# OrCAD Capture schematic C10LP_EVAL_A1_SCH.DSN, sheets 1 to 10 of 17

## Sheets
1 01. Title, Note, Block Diagram: title: Cyclone 10 LP FPGA Evaluation Kit Board; rev: A1; note: 150-0321321-A1     (6XX-44504R)
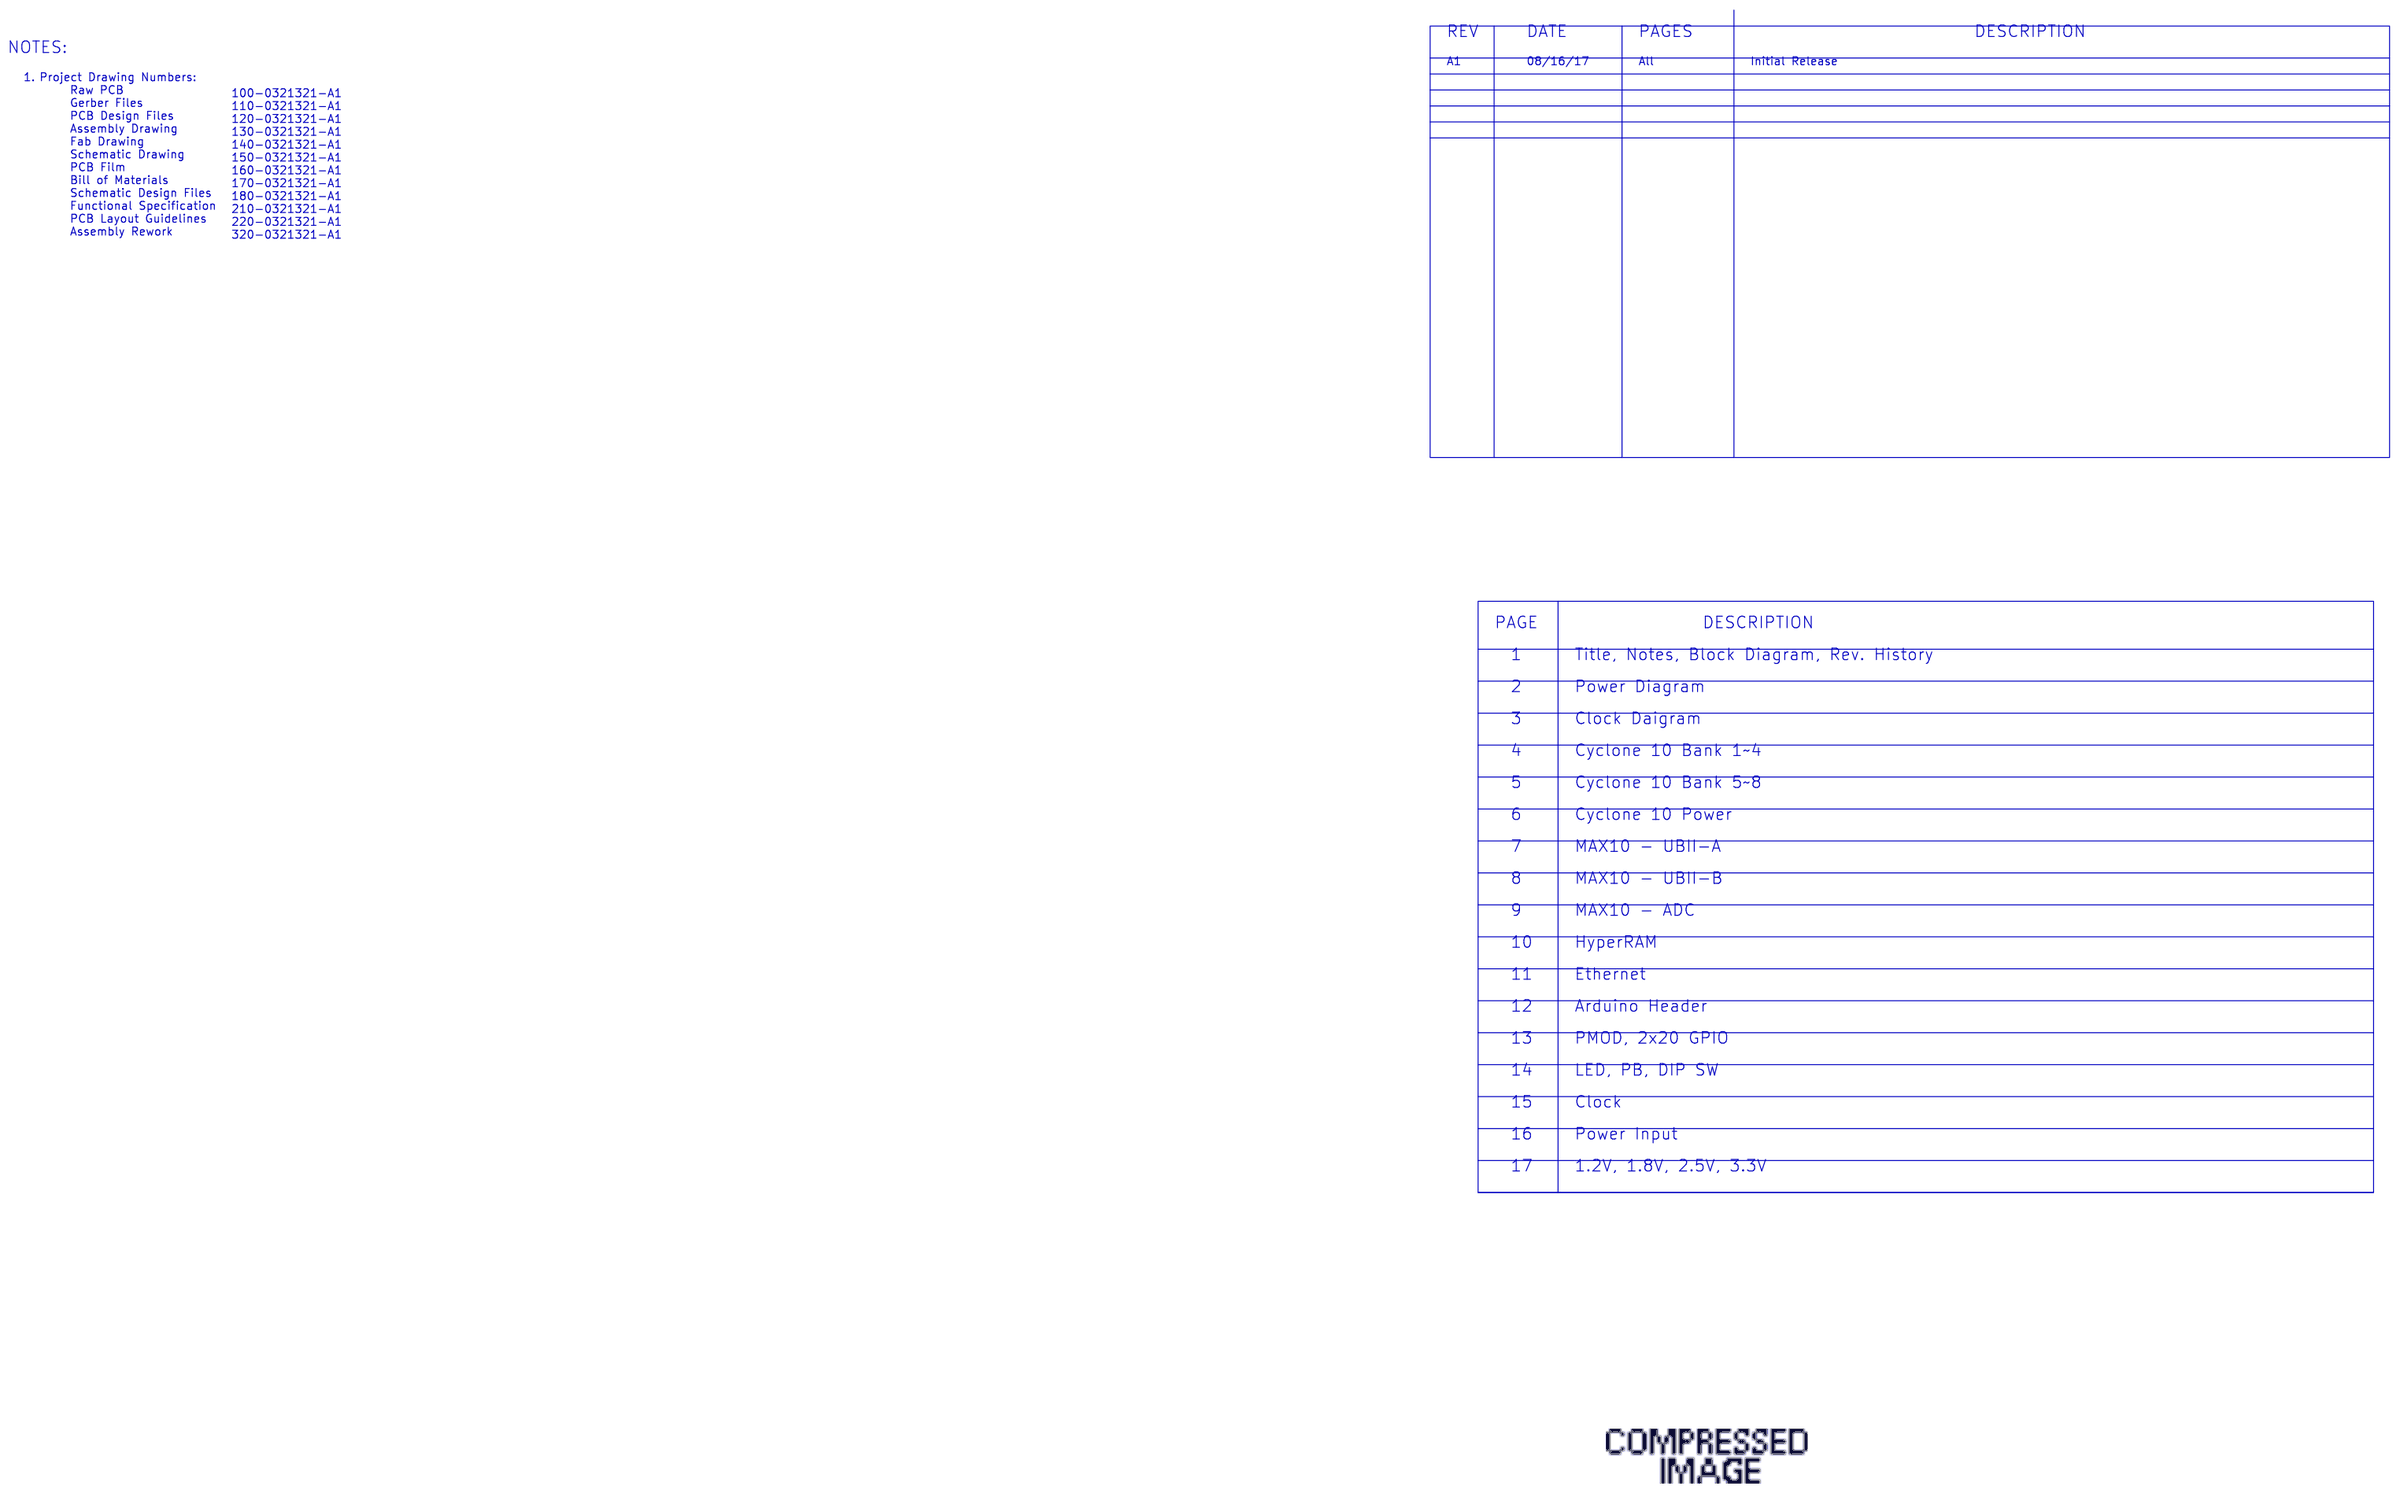
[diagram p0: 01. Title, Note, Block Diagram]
2 02. Power Diagram
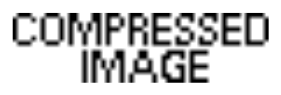
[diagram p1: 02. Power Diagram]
3 03. Clock Daigram
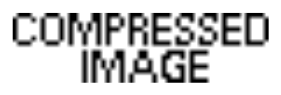
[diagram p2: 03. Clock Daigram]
4 04. Cyclone 10 Bank 1~4: size B
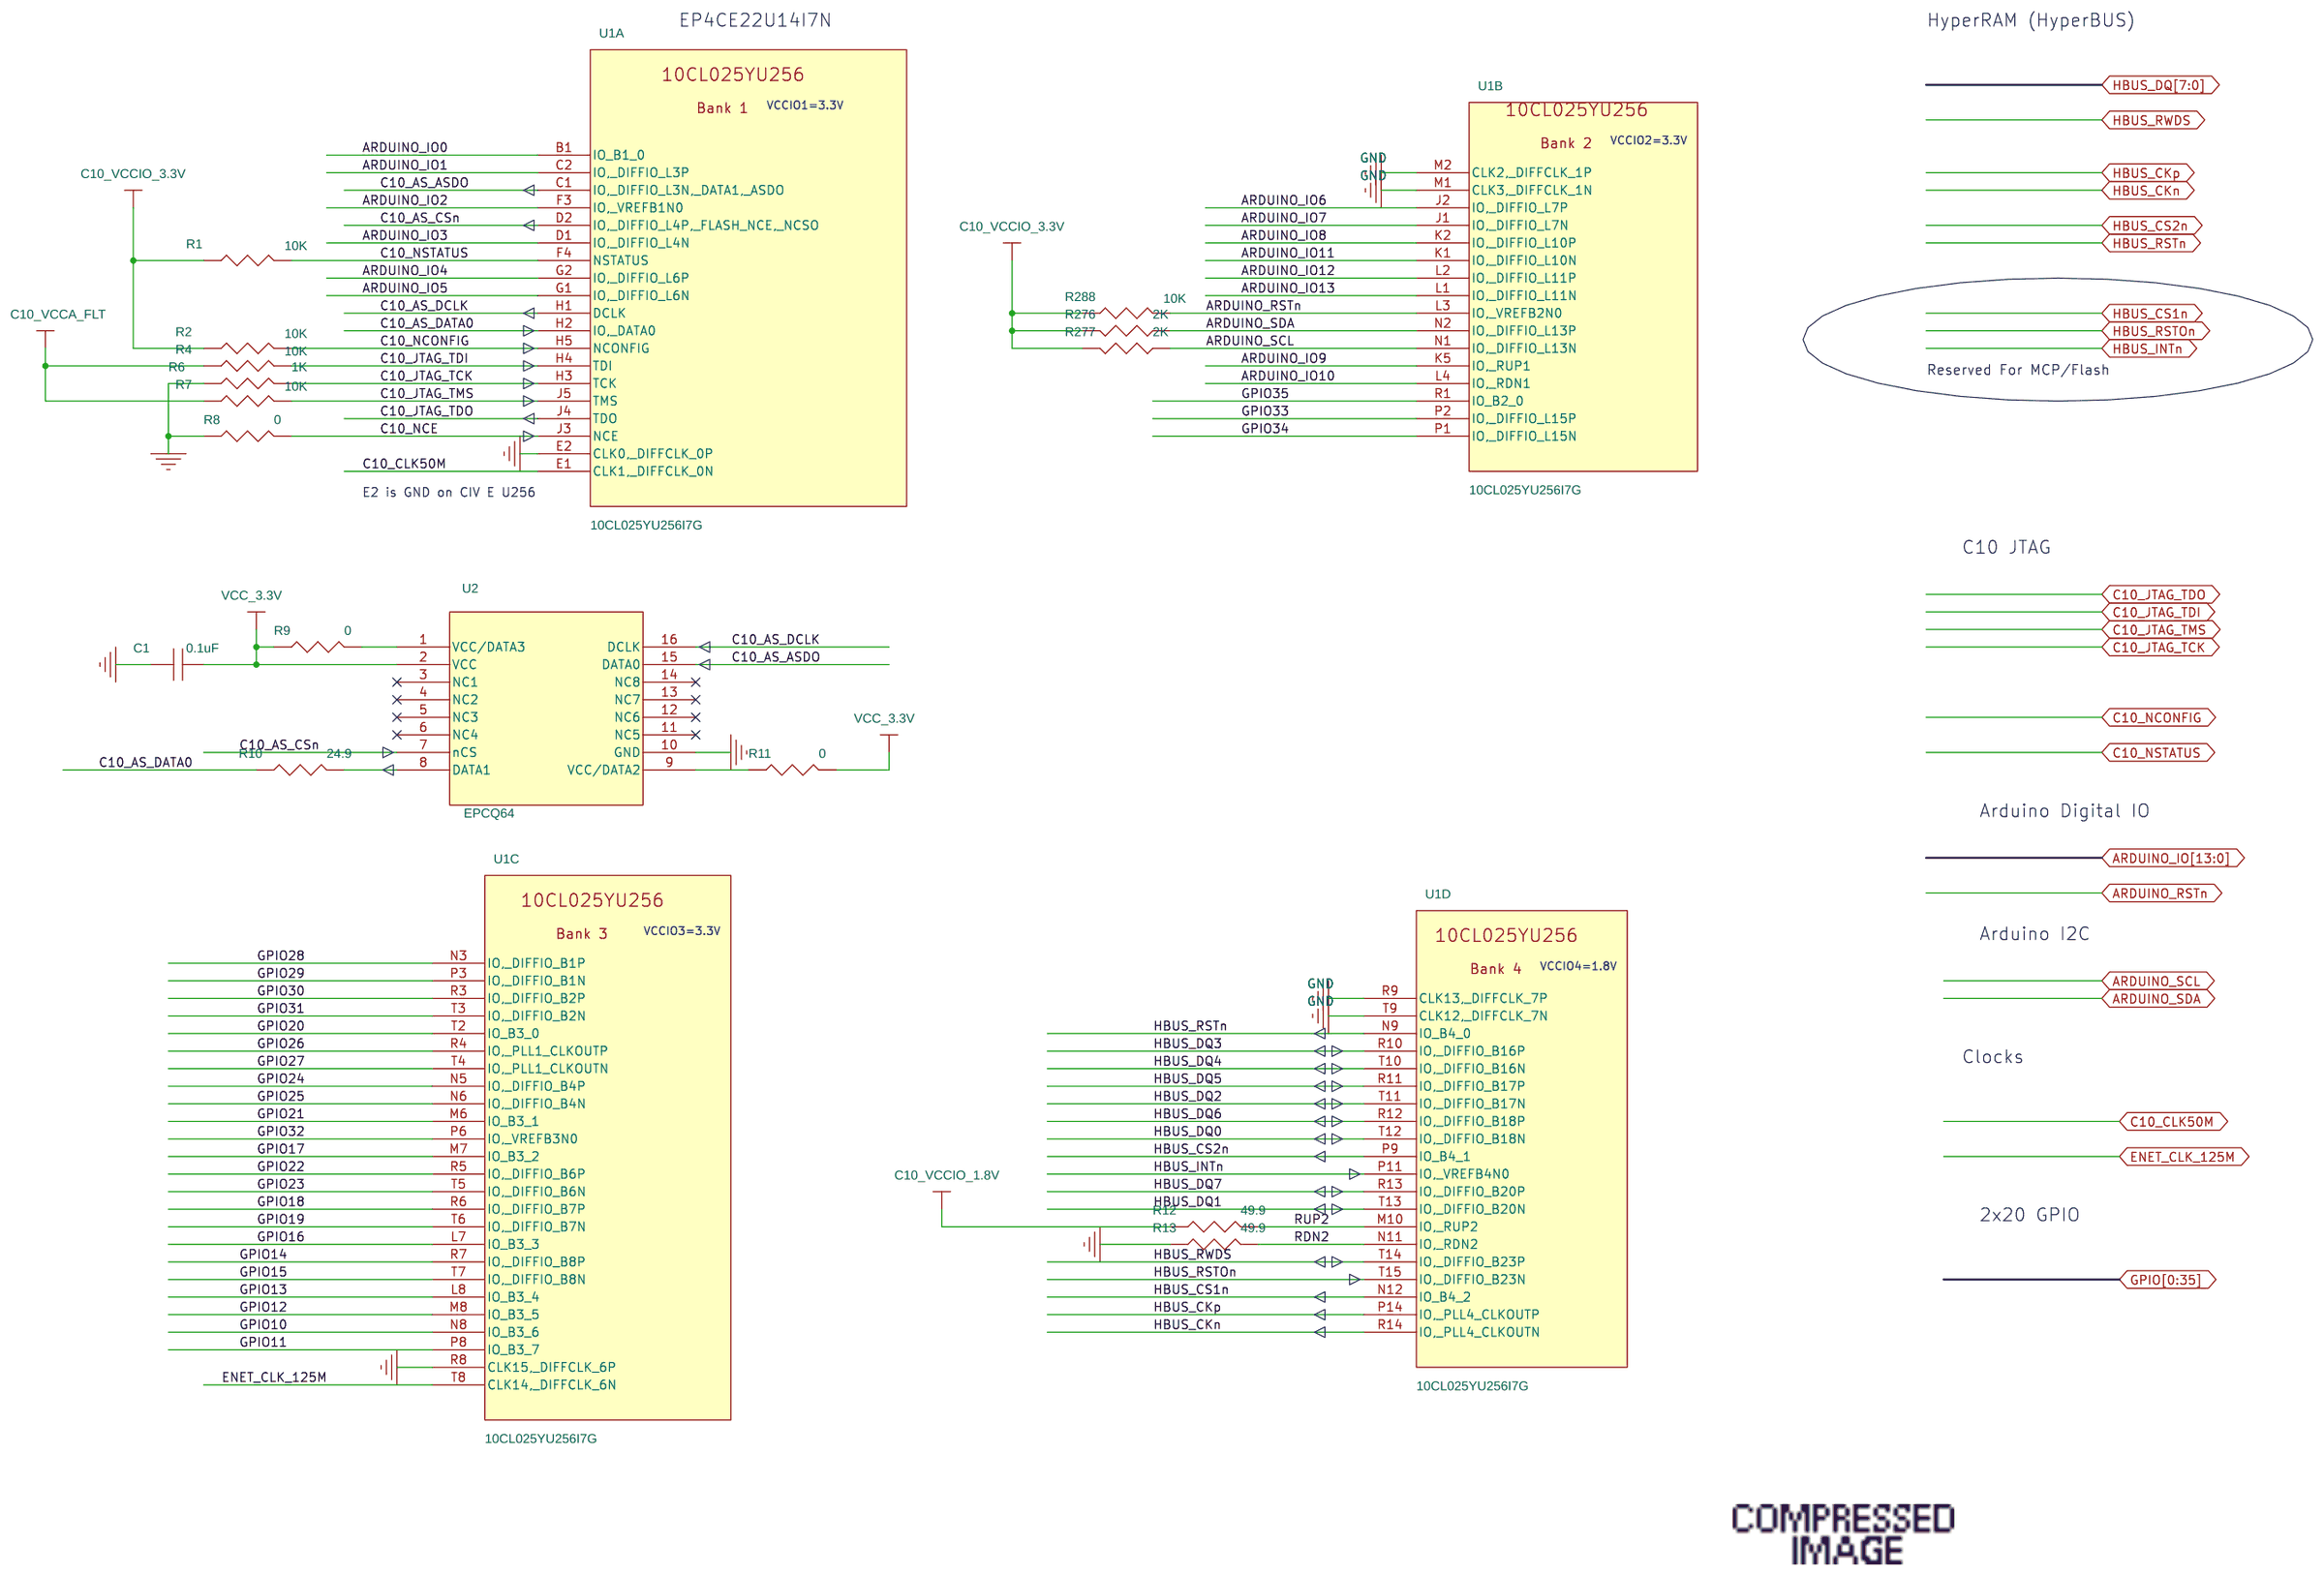
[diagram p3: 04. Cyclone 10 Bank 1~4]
5 05. Cyclone 10 Bank 5~8: size B
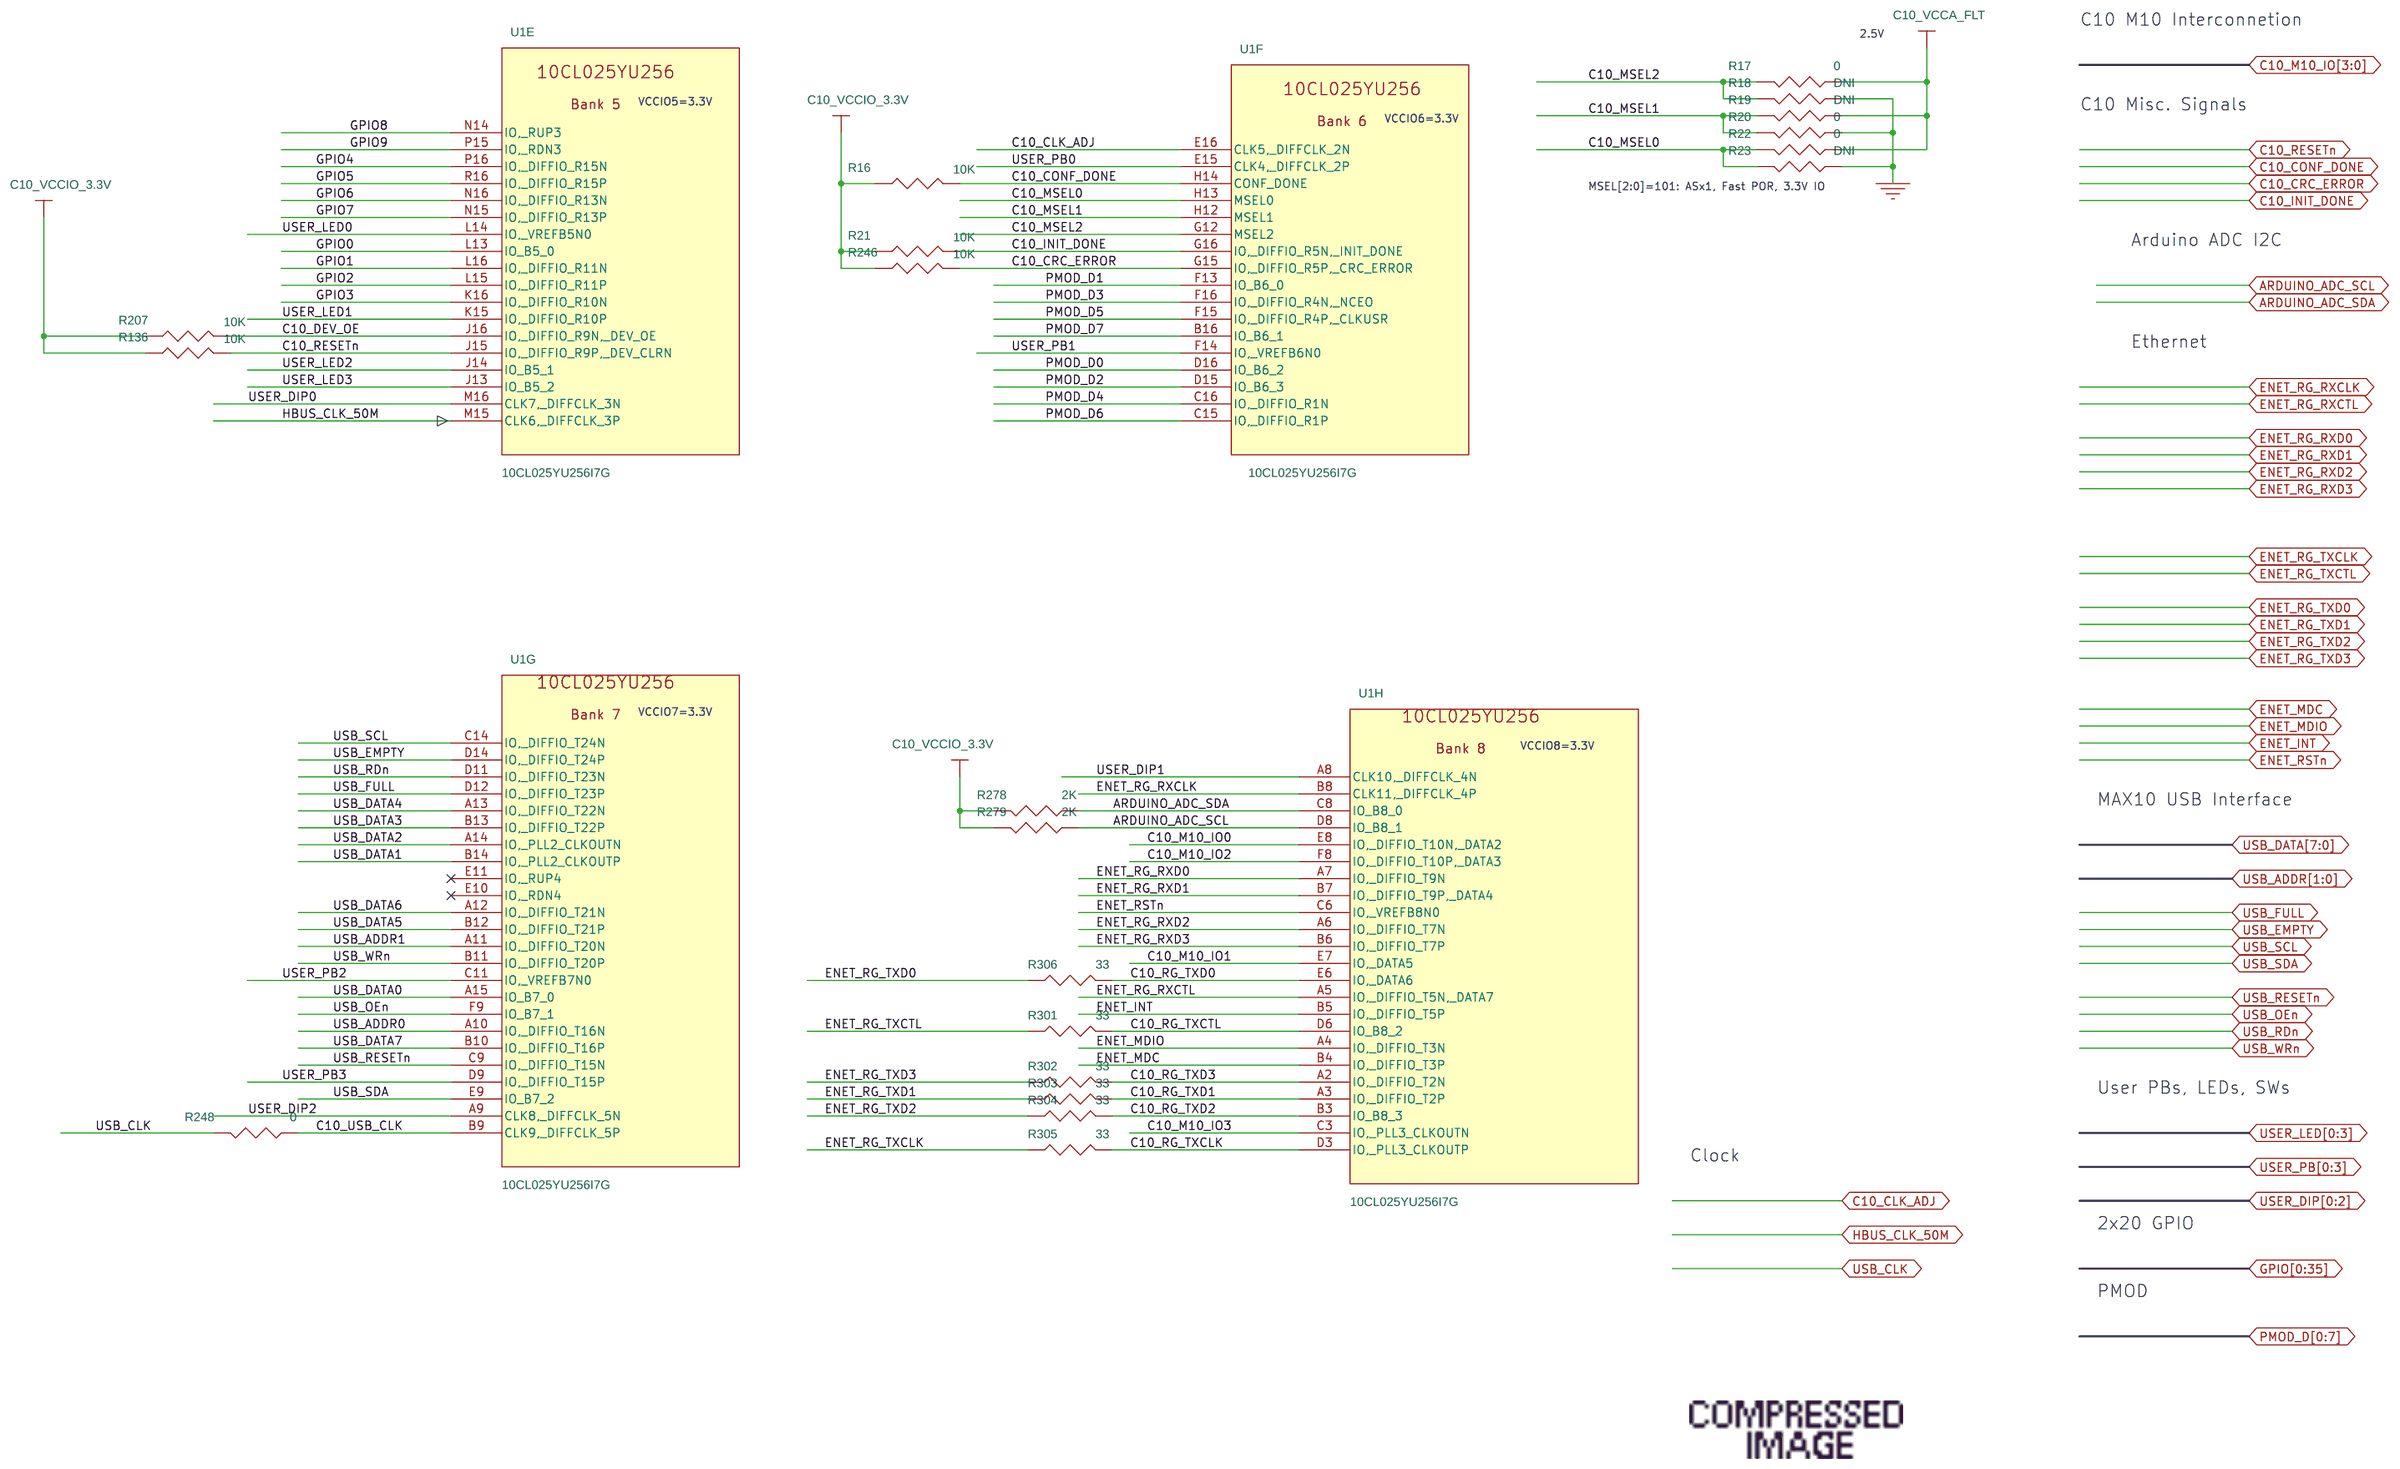
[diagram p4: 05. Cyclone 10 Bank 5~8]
6 06. Cyclone 10 Power: size B
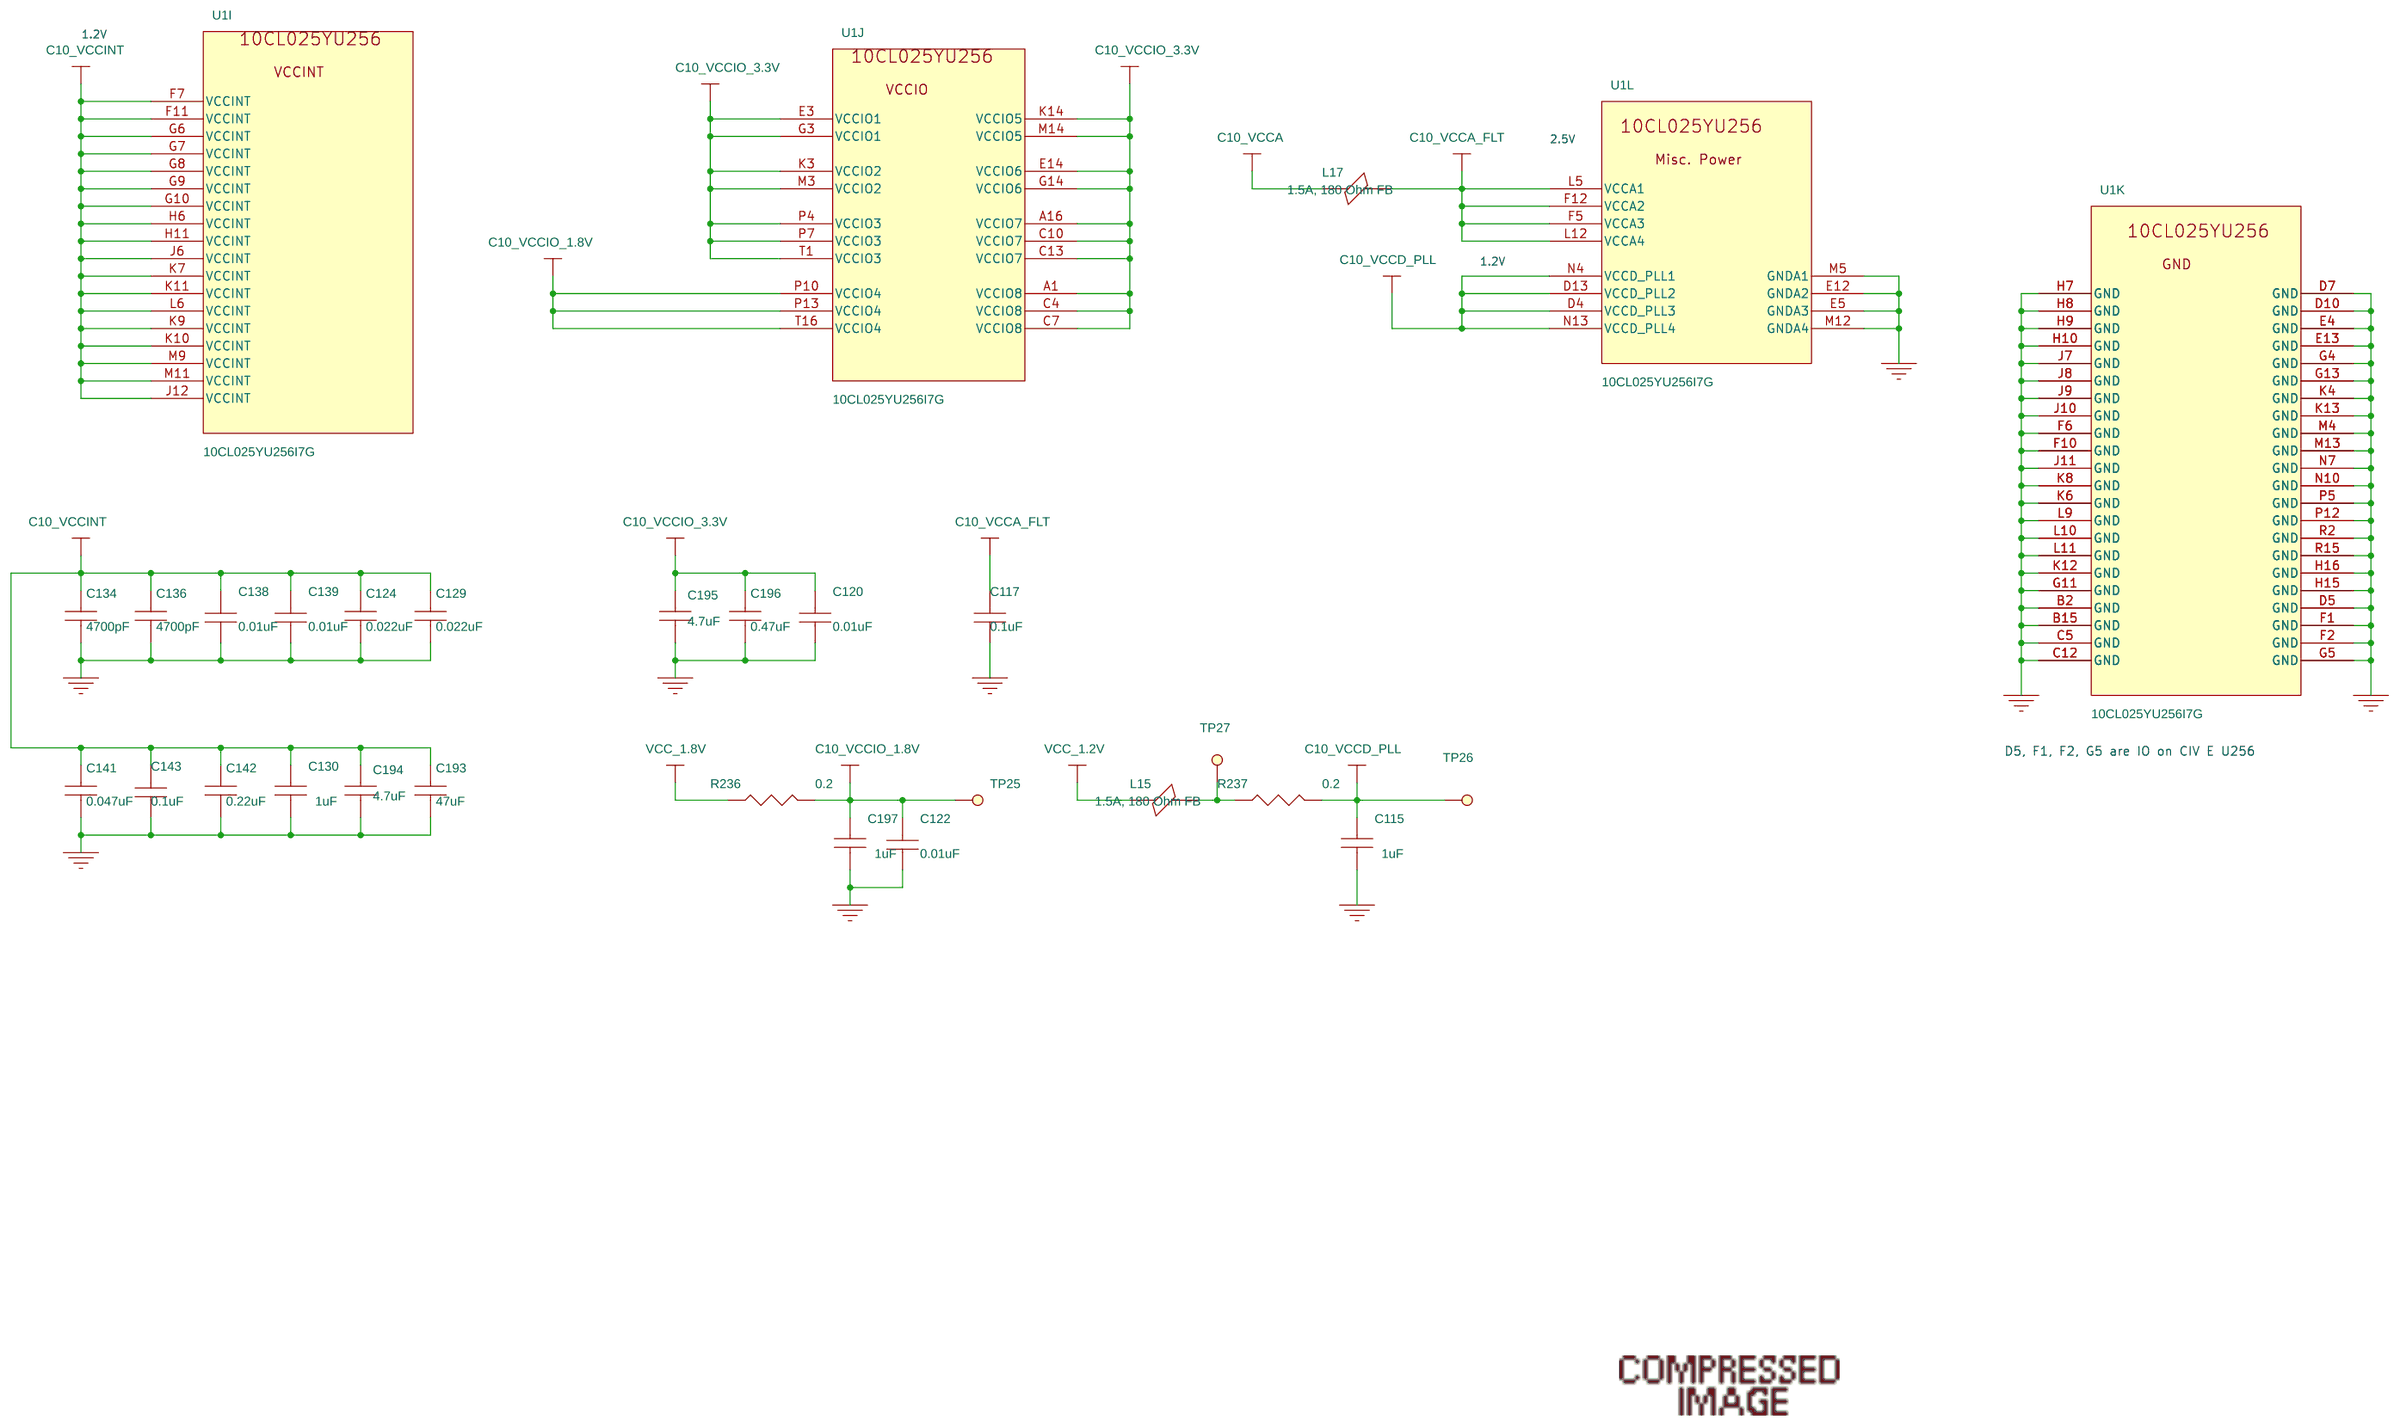
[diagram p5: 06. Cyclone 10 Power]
7 07. MAX10 - UBII-A: size B
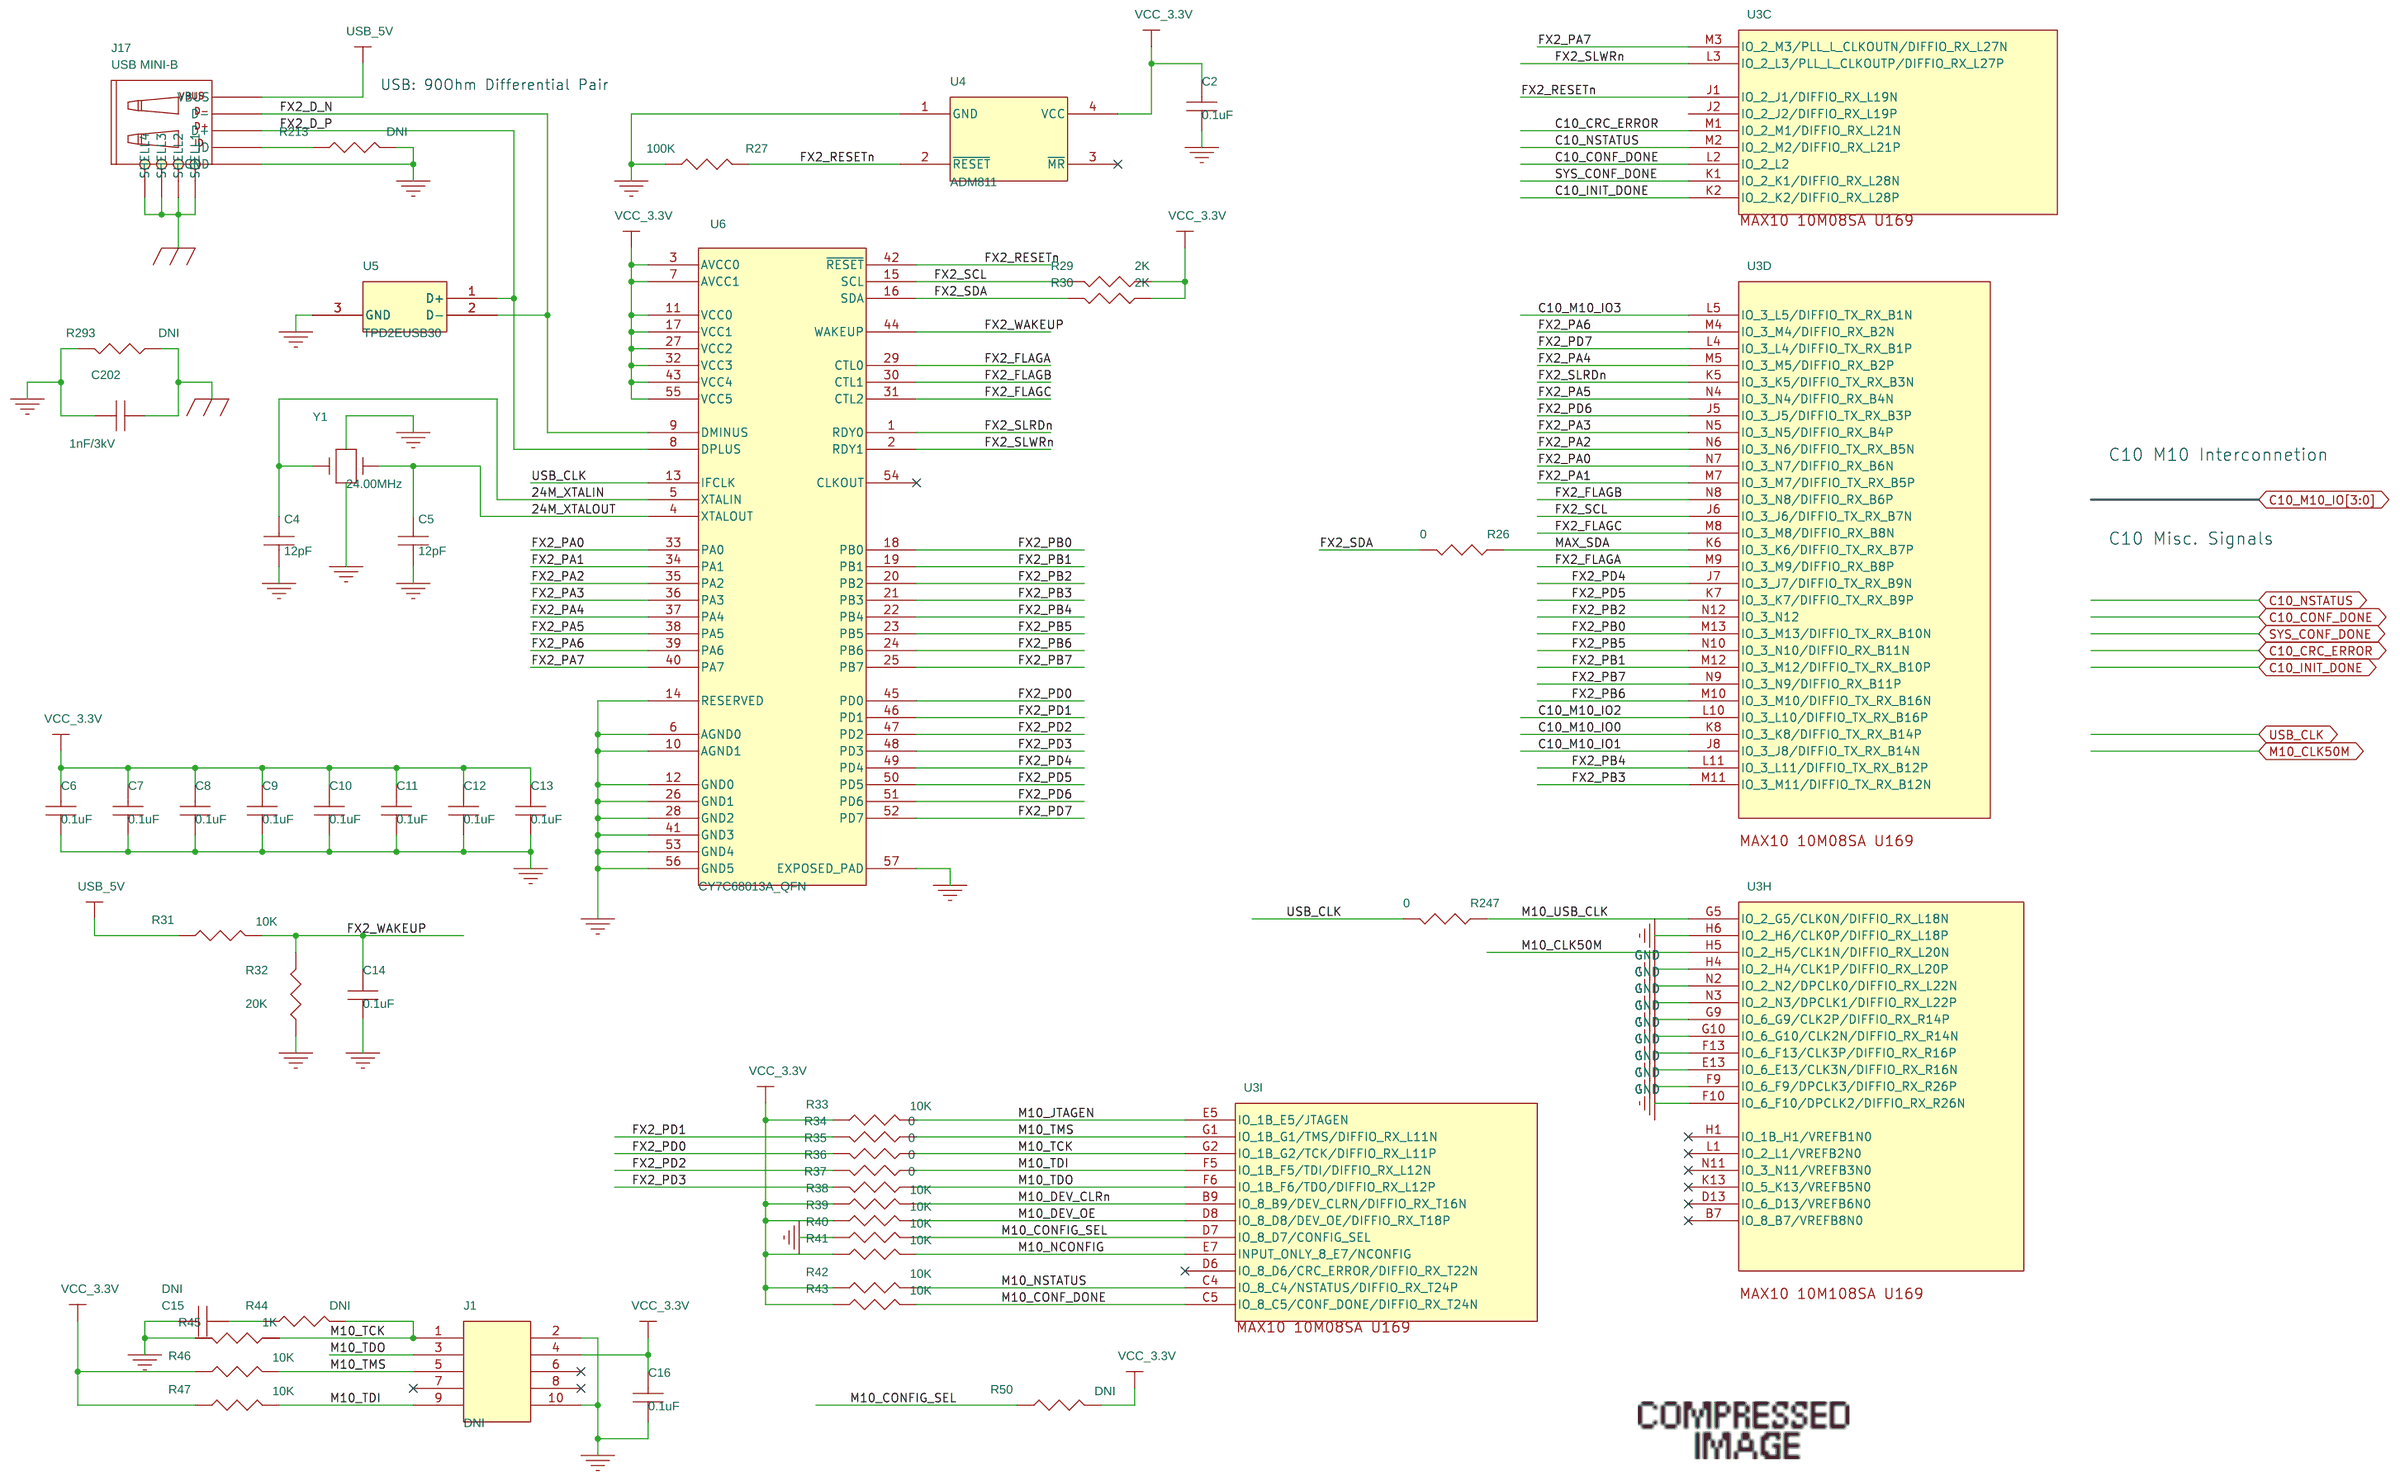
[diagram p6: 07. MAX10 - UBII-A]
8 08. MAX10 - UBII-B: size B
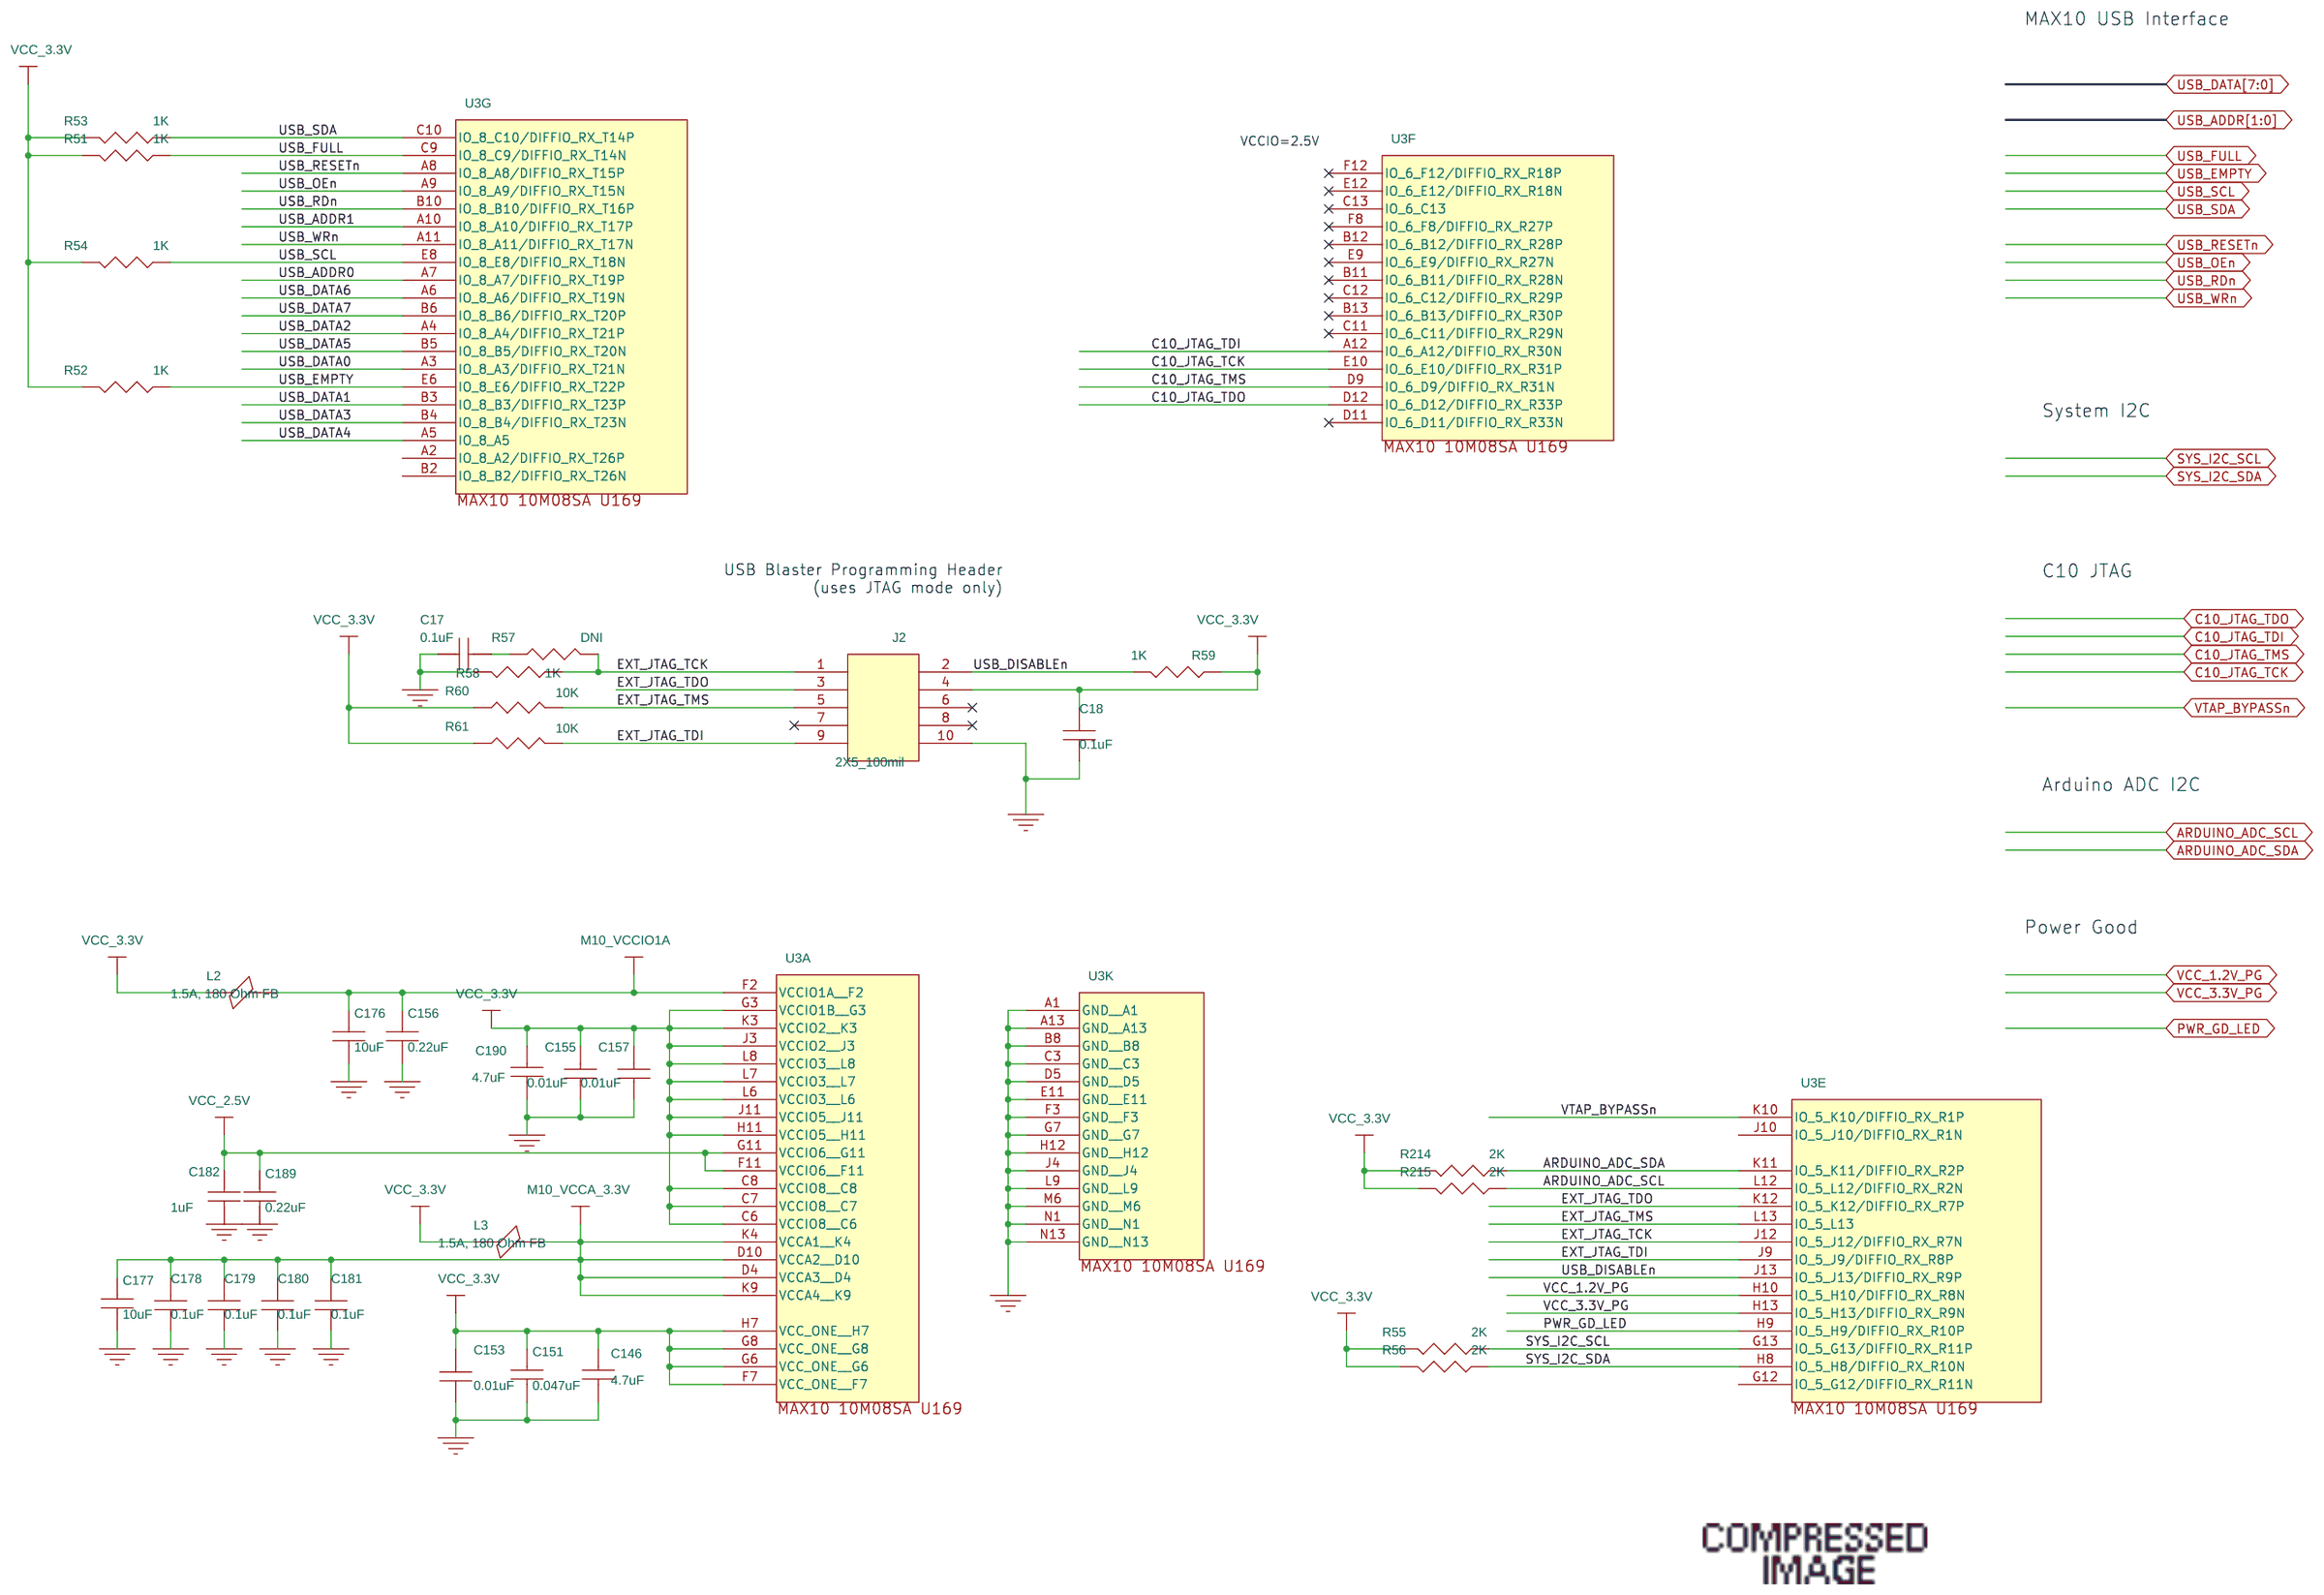
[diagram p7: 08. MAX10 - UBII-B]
9 09. MAX10 - ADC: size B
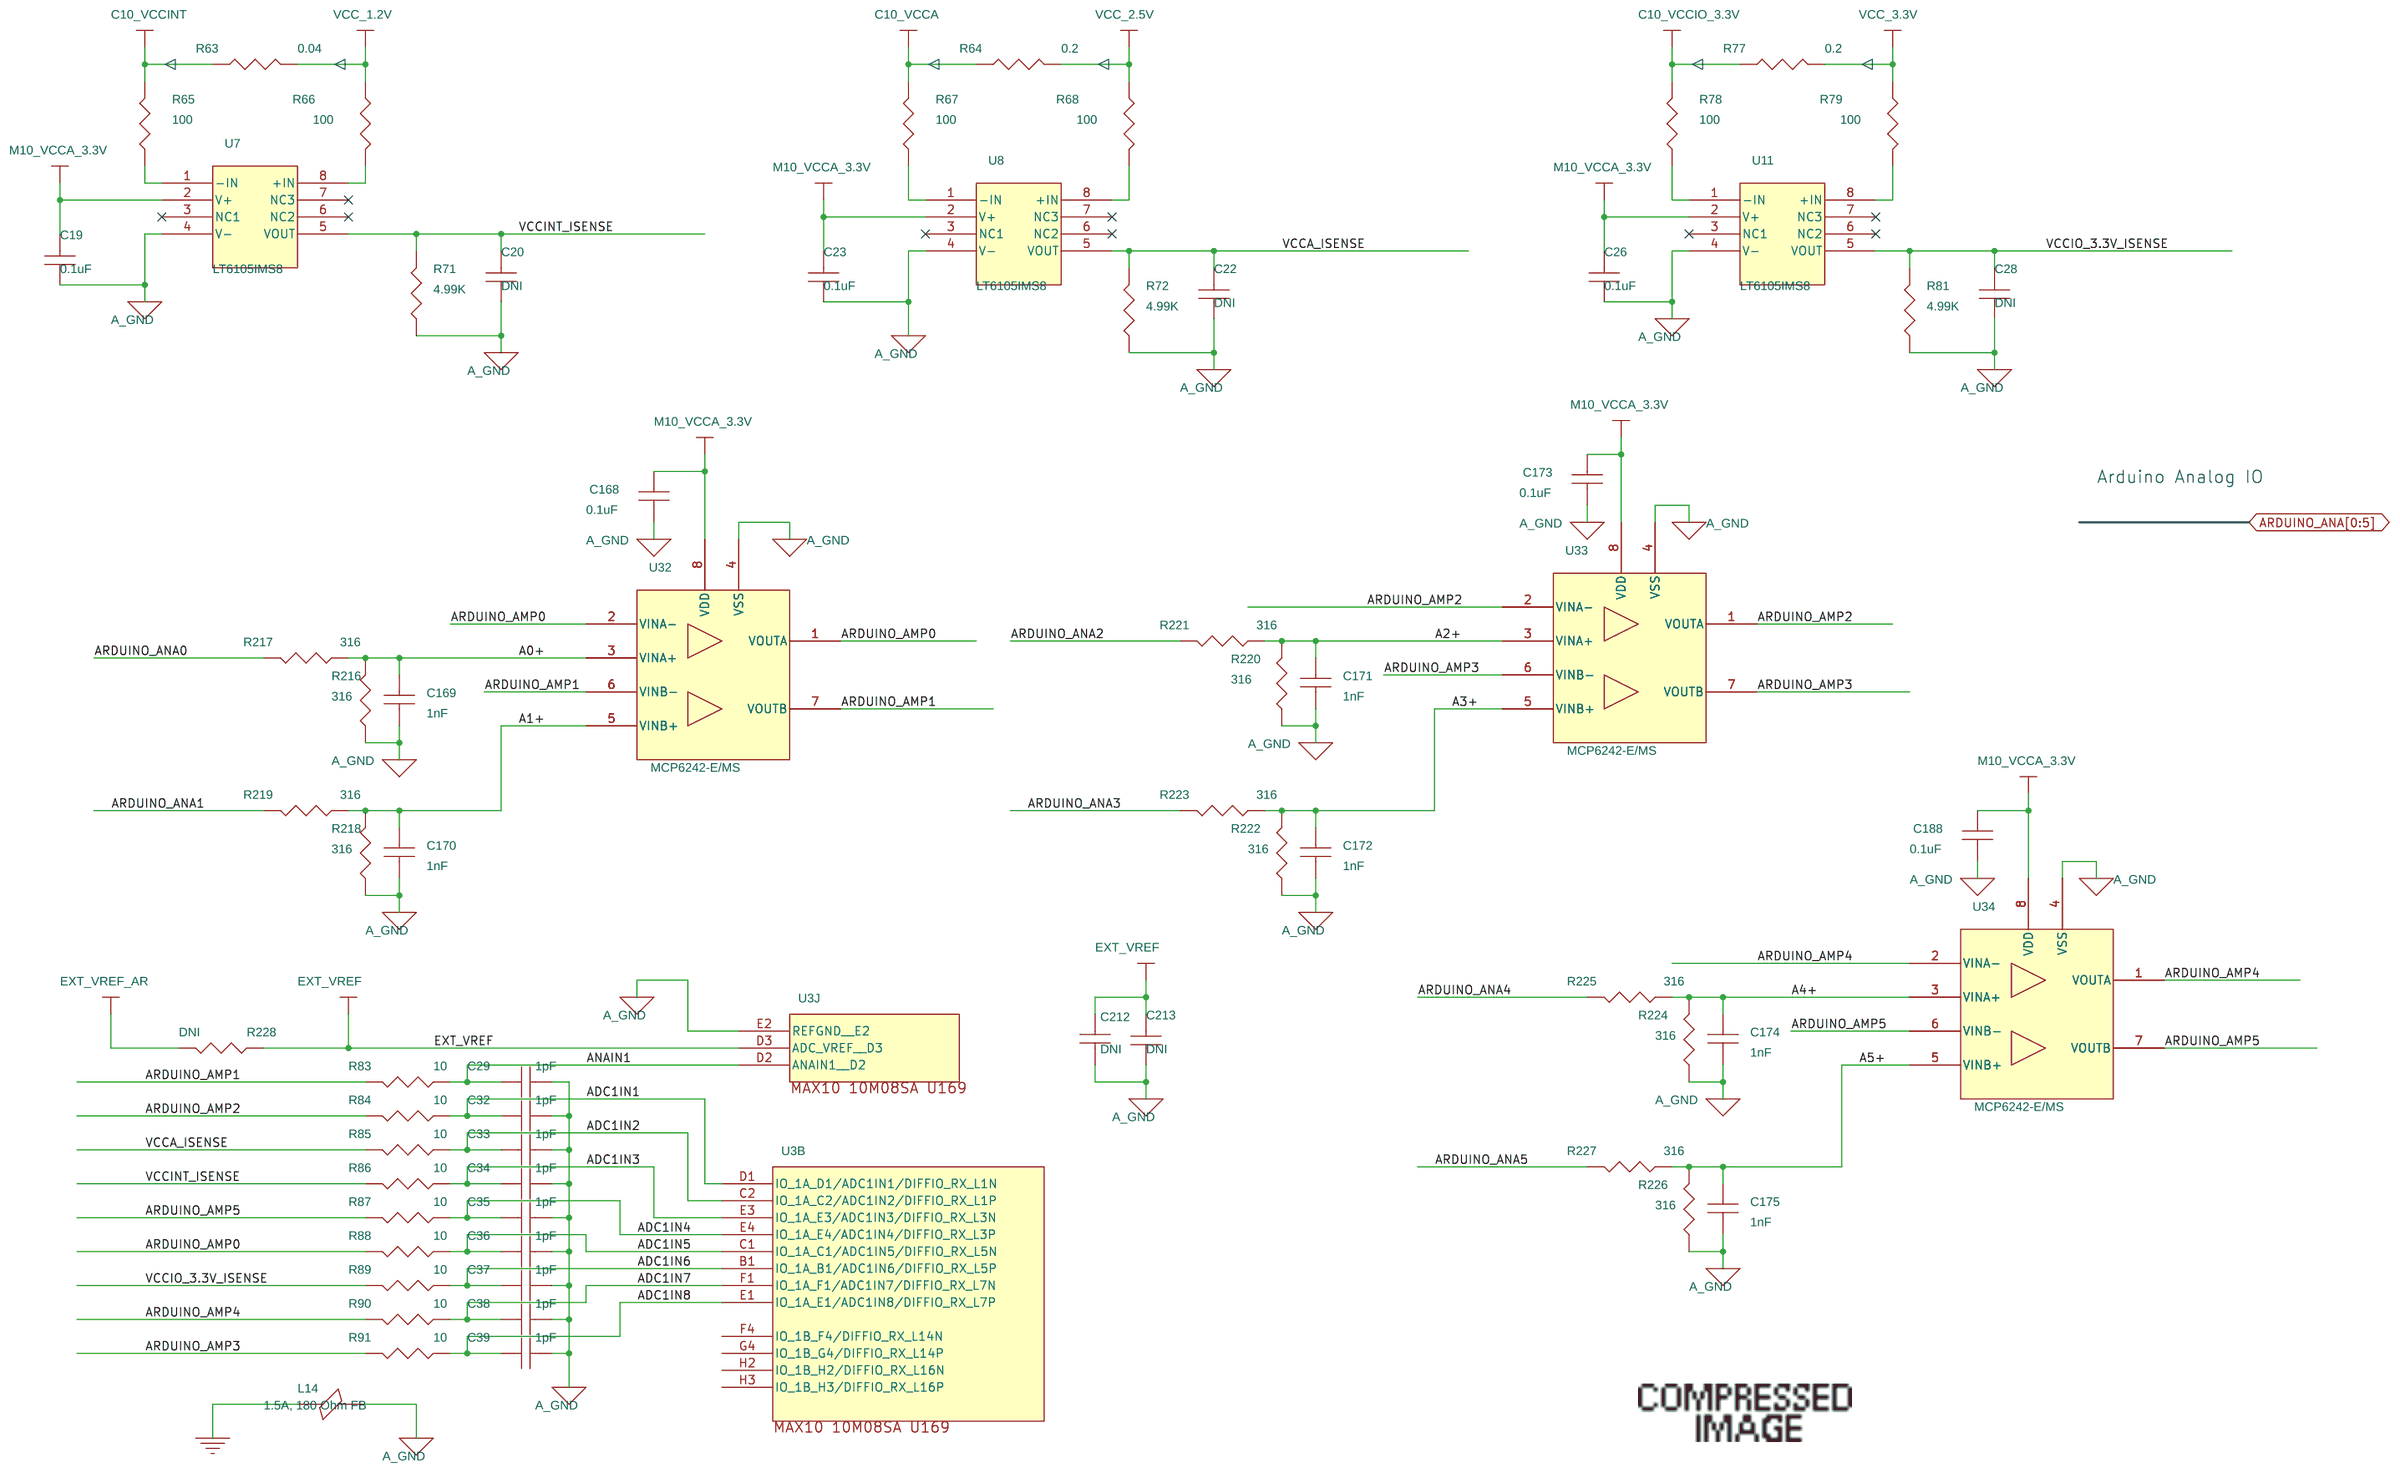
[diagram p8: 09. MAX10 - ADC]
10 10. HyperRAM: size B
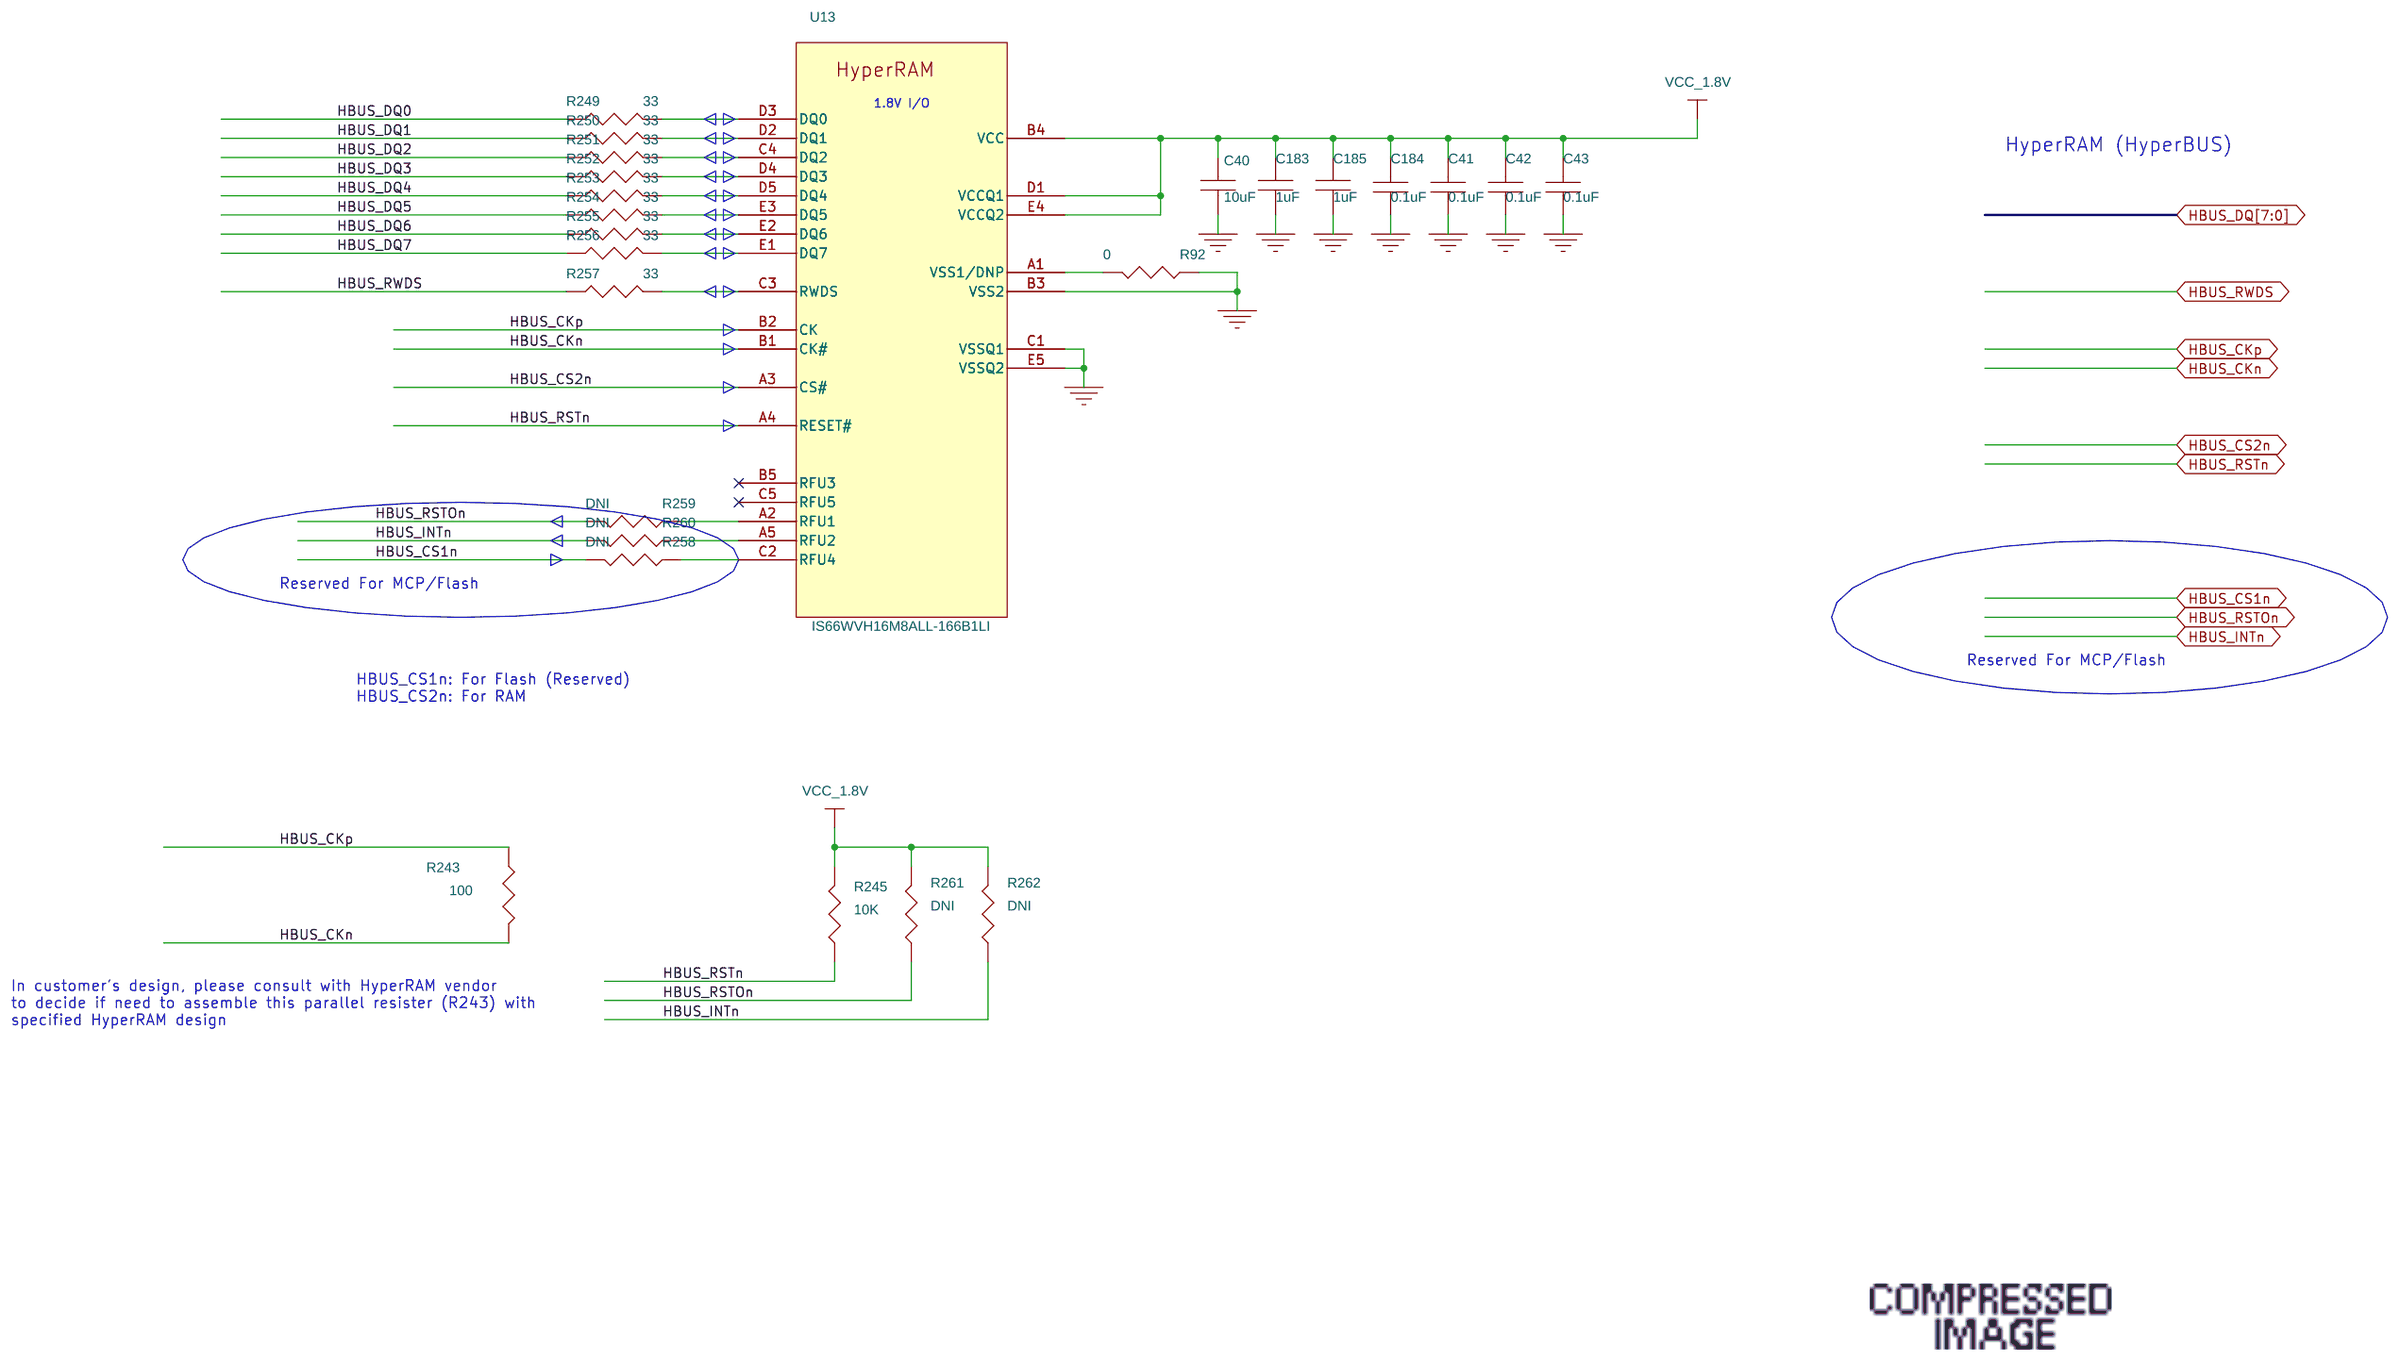
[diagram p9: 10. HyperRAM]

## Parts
sheet 04. Cyclone 10 Bank 1~4
C1  0.1uF  [0402]
R1  10K  [0402]
R2  10K  [0402]
R4  10K  [0402]
R6  1K  [0402]
R7  10K  [0402]
R8  0  [0402]
R9  0  [0402]
R10  24.9  [0402]
R11  0  [0402]
R12  49.9  [0402]
R13  49.9  [0402]
R276  2K  [0402]
R277  2K  [0402]
R288  10K  [0402]
U2  EPCQ64  [SOIC-16_EPCQ]
sheet 05. Cyclone 10 Bank 5~8
R16  10K  [0402]
R17  0  [0402]
R18  DNI  [0402]
R19  DNI  [0402]
R20  0  [0402]
R21  10K  [0402]
R22  0  [0402]
R23  DNI  [0402]
R136  10K  [0402]
R207  10K  [0402]
R246  10K  [0402]
R248  0  [0402]
R278  2K  [0402]
R279  2K  [0402]
R301  33  [0402]
R302  33  [0402]
R303  33  [0402]
R304  33  [0402]
R305  33  [0402]
R306  33  [0402]
U1  10CL025YU256I7G  [U256]  (sections A,B,C,D,E,F,G,H,I,J,K,L)
sheet 06. Cyclone 10 Power
C115  1uF  [C0402_BGA]
C117  0.1uF  [C0402_BGA]
C120  0.01uF  [C0402_BGA]
C122  0.01uF  [C0402_BGA]
C124  0.022uF  [C0402_BGA]
C129  0.022uF  [C0402_BGA]
C130  1uF  [C0402_BGA]
C134  4700pF  [C0402_BGA]
C136  4700pF  [C0402_BGA]
C138  0.01uF  [C0402_BGA]
C139  0.01uF  [C0402_BGA]
C141  0.047uF  [C0402_BGA]
C142  0.22uF  [C0402_BGA]
C143  0.1uF  [C0402_BGA]
C193  47uF  [0805]
C194  4.7uF  [0603]
C195  4.7uF  [0603]
C196  0.47uF  [C0402_BGA]
C197  1uF  [C0402_BGA]
L15  1.5A, 180 Ohm FB  [ind_0603]
L17  1.5A, 180 Ohm FB  [ind_0603]
R236  0.2  [0805]
R237  0.2  [0805]
TP25  VIA_1  [TP_040RD_SMT]
TP26  VIA_1  [TP_040RD_SMT]
TP27  VIA_1  [TP_040RD_SMT]
sheet 07. MAX10 - UBII-A
C2  0.1uF  [0402]
C4  12pF  [0402]
C5  12pF  [0402]
C6  0.1uF  [0402]
C7  0.1uF  [0402]
C8  0.1uF  [0402]
C9  0.1uF  [0402]
C10  0.1uF  [0402]
C11  0.1uF  [0402]
C12  0.1uF  [0402]
C13  0.1uF  [0402]
C14  0.1uF  [0402]
C15  DNI  [0402]
C16  0.1uF  [0402]
C202  1nF/3kV  [1808]
J1  DNI  [hdr2x5_100mil_smt]
J17  USB MINI-B  [Wurth_USB_MINI-B]
R26  0  [0402]
R27  100K  [0402]
R29  2K  [0402]
R30  2K  [0402]
R31  10K  [0402]
R32  20K  [0402]
R33  10K  [0402]
R34  0  [0402]
R35  0  [0402]
R36  0  [0402]
R37  0  [0402]
R38  10K  [0402]
R39  10K  [0402]
R40  10K  [0402]
R41  10K  [0402]
R42  10K  [0402]
R43  10K  [0402]
R44  DNI  [0402]
R45  1K  [0402]
R46  10K  [0402]
R47  10K  [0402]
R50  DNI  [0402]
R213  DNI  [0402]
R247  0  [0402]
R293  DNI  [1206]
U4  ADM811  [SOT-143]
U5  TPD2EUSB30  [DRT]
U6  CY7C68013A_QFN  [QFN56]
Y1  24.00MHz  [XTAL_FA-128]
sheet 08. MAX10 - UBII-B
C17  0.1uF  [0402]
C18  0.1uF  [0402]
C146  4.7uF  [0603]
C151  0.047uF  [C0402_BGA]
C153  0.01uF  [C0402_BGA]
C155  0.01uF  [C0402_BGA]
C156  0.22uF  [C0402_BGA]
C157  0.01uF  [C0402_BGA]
C176  10uF  [0603]
C177  10uF  [0603]
C178  0.1uF  [C0402_BGA]
C179  0.1uF  [C0402_BGA]
C180  0.1uF  [C0402_BGA]
C181  0.1uF  [C0402_BGA]
C182  1uF  [C0402_BGA]
C189  0.22uF  [C0402_BGA]
C190  4.7uF  [0603]
J2  2X5_100mil  [hdr2x5_100mil_smt]
L2  1.5A, 180 Ohm FB  [ind_0603]
L3  1.5A, 180 Ohm FB  [ind_0603]
R51  1K  [0402]
R52  1K  [0402]
R53  1K  [0402]
R54  1K  [0402]
R55  2K  [0402]
R56  2K  [0402]
R57  DNI  [0402]
R58  1K  [0402]
R59  1K  [0402]
R60  10K  [0402]
R61  10K  [0402]
R214  2K  [0402]
R215  2K  [0402]
sheet 09. MAX10 - ADC
C19  0.1uF  [0402]
C20  DNI  [0402]
C22  DNI  [0402]
C23  0.1uF  [0402]
C26  0.1uF  [0402]
C28  DNI  [0402]
C29  1pF  [0402]
C32  1pF  [0402]
C33  1pF  [0402]
C34  1pF  [0402]
C35  1pF  [0402]
C36  1pF  [0402]
C37  1pF  [0402]
C38  1pF  [0402]
C39  1pF  [0402]
C168  0.1uF  [0402]
C169  1nF  [0402]
C170  1nF  [0402]
C171  1nF  [0402]
C172  1nF  [0402]
C173  0.1uF  [0402]
C174  1nF  [0402]
C175  1nF  [0402]
C188  0.1uF  [0402]
C212  DNI  [0603]
C213  DNI  [0402]
L14  1.5A, 180 Ohm FB  [ind_0603]
R63  0.04  [0805]
R64  0.2  [0805]
R65  100  [0402]
R66  100  [0402]
R67  100  [0402]
R68  100  [0402]
R71  4.99K  [0402]
R72  4.99K  [0402]
R77  0.2  [0805]
R78  100  [0402]
R79  100  [0402]
R81  4.99K  [0402]
R83  10  [0402]
R84  10  [0402]
R85  10  [0402]
R86  10  [0402]
R87  10  [0402]
R88  10  [0402]
R89  10  [0402]
R90  10  [0402]
R91  10  [0402]
R216  316  [0402]
R217  316  [0402]
R218  316  [0402]
R219  316  [0402]
R220  316  [0402]
R221  316  [0402]
R222  316  [0402]
R223  316  [0402]
R224  316  [0402]
R225  316  [0402]
R226  316  [0402]
R227  316  [0402]
R228  DNI  [0402]
U3  10M08SAU169  [BGA169-0R80-11X11]  (sections A,B,C,D,E,F,G,H,I,J,K)
U7  LT6105IMS8  [MSOP-8]
U8  LT6105IMS8  [MSOP-8]
U11  LT6105IMS8  [MSOP-8]
U32  MCP6242-E/MS  [MSOP-8]
U33  MCP6242-E/MS  [MSOP-8]
U34  MCP6242-E/MS  [MSOP-8]
sheet 10. HyperRAM
C40  10uF  [0603]
C41  0.1uF  [0402]
C42  0.1uF  [0402]
C43  0.1uF  [0402]
C183  1uF  [0402]
C184  0.1uF  [0402]
C185  1uF  [0402]
R92  0  [0402]
R243  100  [0402]
R245  10K  [0402]
R249  33  [0402]
R250  33  [0402]
R251  33  [0402]
R252  33  [0402]
R253  33  [0402]
R254  33  [0402]
R255  33  [0402]
R256  33  [0402]
R257  33  [0402]
R258  DNI  [0402]
R259  DNI  [0402]
R260  DNI  [0402]
R261  DNI  [0402]
R262  DNI  [0402]
U13  IS66WVH16M8ALL-166B1LI  [TFBGA-24_6x8]

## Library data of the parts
C1 C2 C6-C14 C16-C19 C23 C26 C41-C43 C168 C173 C178-C181 C184 C188 = CAP: CAP CER 0.1UF 25V 20% X7R 0402; Item Num: P03-17618R; Manufacturer: MURATA ELECTRONICS NORTH AMERICA; Manufacturer Part Num: GRM155R71E104KE14D; Num Pins: 2; Part Class: CAPACITORS; Price: 0; RoHS Compliant: RoHS Compliant
R1 R2 R4 R7 R16 R21 R31 R33 R38-R43 R46 R47 R50 R60 R61 R136 R207 R245 R246 R261 R262 R288 = RES_10K_OHM_5%_1_16W_0402_SMD
R6 R45 R51-R54 R58 R59 = R: RES - 1K OHM, 1/16W, 1%, 0402, SMD; Item Num: P02-14274R; Manufacturer: Vishay; Manufacturer Part Num: CRCW04021K00FKED; Price: 0; RoHS Compliant: Yes
R8 R9 R11 = RESISTOR: RES ZERO OHM 1/16W 5% 0402 SMD; Altera Part No.: P02-14020R; Item Num: P02-14020R; Lead Free Status: No; Manufacturer: Panasonic; Manufacturer Part Num: ERJ-2GE0R00X; Num Pins: 2; Part Class: RESISTORS; RoHS Compliant: Yes; Tolerance: 5%
R10 = RES_24.9_OHM_1%_1_16W_0402: RES - 24.9 OHMS, 1%, 1/16W,0402
R12 R13 = RES_49.9_OHM_1%_1_16W_0402
R29 R30 R55 R56 R214 R215 R276-R279 = RESISTOR: RES,2.00K OHMS,1.0%,1/16W,0402; Item Num: P02-11376R; Manufacturer: Panasonic; Manufacturer Part Num: ERJ-2RKF2001X; Price: 0
U2 = EPCQ128: IC CONFIG DEVICE (EPCQ) 64MBIT 16SOIC; Item Num: P01-18138R; Manufacturer: Intel; Manufacturer Part Num: EPCQ64SI16N
R17 R20 R22 R26 R34-R37 R92 R247 R248 = RESISTOR: RES ZERO OHM 1/16W 5% 0402 SMD; Item Num: P02-14020R; Lead Free Status: No; Manufacturer: Panasonic; Manufacturer Part Num: ERJ-2GE0R00X; Num Pins: 2; Part Class: Resistors; RoHS Compliant: Yes
R18 R19 R23 R228 R258-R260 = RESISTOR: RES ZERO OHM 1/16W 5% 0402 SMD; Item Num: P02-14020R; Lead Free Status: No; Manufacturer: Panasonic; Manufacturer Part Num: ERJ-2GE0R00X; Num Pins: 2; Part Class: Resistors; Price: 0; RoHS Compliant: Yes
R249-R257 R301-R306 = RESISTOR: RES 33 OHM 1/16W 5% 0402 SMD; Altera Part No.: P02-14020R; Item Num: P02-14029R; Manufacturer: Panasonic; Manufacturer Part Num: ERJ-2GEJ330X
U1 = 10CL025YU256I7G: IC - CYCLONE 10 LP FPGA, 10CL025YU256I7G, 25K LES, U256 BGA, LEADFREE; Item Num: P01-18144R; Manufacturer: Intel
C115 C130 C182 C183 C185 C197 = CAP_1.0UF_10%_10V_0402: Manufacturer: Murata; Manufacturer Part Num: GRM155R61A105KE15D
C117 C143 = CAP: CAP CER 0.1UF 25V 20% X7R 0402; Item Num: P03-17618R; Manufacturer: MURATA ELECTRONICS NORTH AMERICA; Manufacturer Part Num: GRM155R71E104KE14D
C120 C122 C138 C139 C153 C155 C157 = CAP: CAP - CER, 10NF, 50V, +/-10%, X7R, 0402 SMD; Dielectric: X5R; Item Num: P03-16318R; Manufacturer: Murata; Manufacturer Part Num: GRM155R71H103KA88D
C124 C129 = CAP: CAP - CER 0.022UF, 10V, 10%, X5R, 0402; Item Num: P03-17676R; Manufacturer: Murata; Manufacturer Part Num: GRM155R61A223KA01D
C134 C136 = CAP: CAP - CER 4700PF 50V 10% X7R 0402; Item Num: P03-15074R; Manufacturer: Murata; Manufacturer Part Num: GRM155R71H472KA01D
C141 C151 = CAP: CAP, CERAMIC, 0.047UF, 10%, X7R, 16V, 0402; Item Num: P03-17659R; Manufacturer: Murata; Manufacturer Part Num: GRM155R71C473KA01D
C142 C156 C189 = CAP: CAP - CERAMIC, 0.22UF, 10V, X5R, 10%, 0402; Item Num: P03-15149R; Manufacturer: Murata; Manufacturer Part Num: GRM155R61A224KE19D
C193 = CAP: CAP - CER 47UF, 10V, 20%, X5R, +/-20%, 0805; Item Num: P03-17686R; Manufacturer: TDK Electronics; Manufacturer Part Num: C2012X5R1A476M125AC
C146 C190 C194 C195 = Cap_0.1UF_+_-10%_10V_0402: CAP - CER 4.7UF, 25V, 10%, X5R, 0603; Item Num: P03-17677R; Manufacturer: Murata; Manufacturer Part Num: GRM188R61E475KE11D
C196 = CAP: CAP - CER, 0.47UF, 10%, 6.3V, X5R, 0402; Item Num: P03-15172R; Manufacturer: Murata; Manufacturer Part Num: RM155R60J474KE19D
L2 L3 L14 L15 L17 = IND_Ferrite_0603_3A_30_Ohms: IND - SMD EMI FILTERS/CHIP FERRITE BEAD, 180-OHM @ 100MHZ, 0.09-OHM DCR, 1.5A, 0603; Item Num: P04-17069R; Manufacturer Part Num: 742792624
R64 R77 R236 R237 = RESISTOR: RES  0.2 OHM 1% 1/3W 0805 SMD; Item Num: P02-17884R; Lead Free Status: Yes; Manufacturer: Panasonic; Manufacturer Part Num: ERJ-6BSFR20V; Num Pins: 2; Part Class: Resistors; Price: 0; RoHS Compliant: Yes
TP25-TP27 = VIA_1
C4 C5 = CAP: CAP - 12PF, 50V, +/-5%, CERAMIC, 0402 SMD; Item Num: P03-15352R; Manufacturer: Murata; Manufacturer Part Num: GRM1555C1H120JA01D; RoHS Compliant: RoHS Compliant
C15 C20 C22 C28 C213 = CAP: CAP CER 0.1UF 25V 20% X7R 0402; CAPACITANCE: 0.1uF; Item Num: P03-17618R; Manufacturer: MURATA ELECTRONICS NORTH AMERICA; Manufacturer Part Num: GRM155R71E104KE14D; Num Pins: 2; Part Class: CAPACITORS; Price: 0; RoHS Compliant: RoHS Compliant
C202 = CAP: CAP CER 1000PF 3KV X7R 1808; Item Num: P03-17908R; Manufacturer: Yageo; Manufacturer Part Num: CC1808KKX7REBB102
J1 J2 = 2x5: CONN - CONN HEADER VERT DUAL 10POS 2.54MM; Item Num: P23-38640R; Lead Free Status: No; Manufacturer: Wurth Elektronik; Manufacturer Part Num: 61001021121; Num Pins: 10; Part Class: Connectors; Price: 0; RoHS Compliant: Yes
J17 = USB_MINI-B: CONN - MINI USB 5POS HORIZ T/H; Item Num: P23-38638R; Manufacturer: Wurth Elektronik; Manufacturer Part Num: 651 005 136 521
R27 = RESISTOR: RES,100K OHMS,1.0%,1/16W,0402; Item Num: P02-11386R; Manufacturer: Panasonic; Manufacturer Part Num: ERJ-2RKF1003X; Price: 0
R32 = RESISTOR: RES 20.0K OHM 1/16W 1% 0402 SMD; Item Num: P02-14071R; Manufacturer: Panasonic; Manufacturer Part Num: ERJ-2RKF2002X
R44 R57 = RESISTOR: RES,10.0K OHMS,1.0%,1/16W, 0402; Item Num: P02-11364R; Manufacturer: Panasonic; Manufacturer Part Num: ERJ-2RKF1002X; Num Pins: 2
R213 = RESISTOR: RES ZERO OHM 1/16W 5% 0402 SMD; Altera Part No.: P02-14020R; Item Num: P02-14020R; Lead Free Status: No; Manufacturer: Panasonic; Manufacturer Part Num: ERJ-2GE0R00X; Num Pins: 2; Part Class: RESISTORS; Price: 0; RoHS Compliant: Yes; Tolerance: 5%
R293 = RESISTOR: RES SMD 1M OHM 1% 1/4W 1206; Item Num: P02-17885R; Manufacturer: Panasonic; Manufacturer Part Num: ERJ-8ENF1004V
U4 = MAX811_0: IC SUPVSR W/RESET 2.93V SOT-143; Item Num: P01-18140R; Manufacturer: Analog Device; Manufacturer Part Num: ADM811SARTZ-REEL7
U5 = TPD2EUSB30_0: DIODE - FULL SPEED USB ESD SOLUTION, 2CH, SOT3; Item Num: P08-20777R; Lead Free Status: Yes; MFR_LIFECYCLE: Active; Manufacturer: Texas Instruments; Manufacturer Part Num: TPD2EUSB30DRxx; Num Pins: 3; Part Class: ICS; RoHS Compliant: Yes
U6 = CY7C68013A_0: IC - EZ-USB FX2LP Microcontroller 400KHz, 56-QFN, 3.3V; Item Num: P01-17739R; Lead Free Status: Yes; Manufacturer: Cypress; Manufacturer Part Num: CY7C68013A-56LTXCx; Num Pins: 57; Part Class: ICs; RoHS Compliant: Yes
Y1 = CRYSTAL_SM_13: CRYSTAL - MINI XTL, 24.00 MHZ, +/-50PPM, +/-30PPM-20~75C, 12PF, 2.0mm x 1.6mm SMD; Item Num: P07-19648R; Lead Free Status: Yes; MFR_LIFECYCLE: Active; Manufacturer: Epson Toyocom; Manufacturer Part Num: FA-128 24.0000MB-W:; Num Pins: 4; RoHS Compliant: Yes
C40 C176 C177 C212 = CAP: CAP - CER 10UF 6.3V 20% X5R 0603; Item Num: P03-15733R; Manufacturer: Murata; Manufacturer Part Num: GRM188R60J106ME47X; RoHS Compliant: RoHS Compliant
C29 C32-C39 = CAP: CAP - CERAMIC, 1PF, +/-0.25PF,  50V, 0402, C0G; Item Num: P03-15104R; Manufacturer: Murata; Manufacturer Part Num: GJM1555C1H1R0CB01D
C169-C172 C174 C175 = CAP: CAP CER 1000PF 50V 10% X7R 0402; Item Num: P03-17756R; Manufacturer: Yageo; Manufacturer Part Num: CC0402KRX7R9BB102; Price: 0
R63 = RESISTOR: RES SMD 0.04 OHM 1% 1/8W 0805; Item Num: P02-17911R; Manufacturer: Vishay Dale; Manufacturer Part Num: WSL0805R0400FEA
R65-R68 R78 R79 R243 = RESISTOR: RES,100 OHMS,1.0%,1/16W,0402; Item Num: P02-11381R; Manufacturer: Panasonic; Manufacturer Part Num: ERJ-2RKF1000X; Price: 0
R71 R72 R81 = RESISTOR: RES 4.99K OHM 1/16W 1% 0402 SMD; Item Num: P02-14129R; Manufacturer: Panasonic; Manufacturer Part Num: ERJ-2RKF4991X; Price: 0
R83-R91 = RES_10_OHM_1.0%_1_16W_0402: RES, 10 OHMS, 1.0%, 1/10W, 0402
R216-R227 = RES_10K_OHM_5%_1_16W_0402_SMD: RES - 316 OHM 1/16W 1% 0402 SMD; Item Num: P02-14349R; Manufacturer Part Num: ERJ-2RKF3160X
U3 = 10M16SA_U169_12: IC - MAX 10 10M08 SINGLE-SUPPLY DEVICE, SINGLE ADC BLOCK, 169-PIN UBGA, 3.0 OR 3.3V SUPPLY; Item Num: P01-18141R; Manufacturer: Intel; Manufacturer Part Num: 10M08SAU169C8G
U7 U8 U11 = LT6105IDCB_0: IC OPAMP CURR SENSE 100KHZ 8MSOP; Item Num: P01-18124R; Manufacturer: Linear Technology; Manufacturer Part Num: LT6105IMS8#PBF
U32-U34 = MCP6242-E_MS: IC OPAMP GP 550KHZ RRO 8MSOP; Item Num: P01-18145R; Manufacturer: Microchip Technology Inc.
U13 = IS66WVH32M8ALL-166BLI_0: 128Mb 16MbX8 1.8V 166MHz HyperRAM; Item Num: P01-18125R; Manufacturer: ISSI

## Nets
GND: C1.2 C2.1 C4.2 C5.2 C6.1 C7.1 C8.1 C9.1 C10.1 C11.1 C12.1 C13.1 C14.1 C15.1 C16.1 C17.1 C18.1 C40.2 C41.1 C42.1 C43.1 C115.2 C117.1 C120.1 C122.1 C124.2 C129.2 C130.2 C134.2 C136.2 C138.1 C139.1 C141.2 C142.2 C143.1 C146.2 C151.2 C153.1 C155.1 C156.2 C157.1 C176.2 C177.2 C178.1 C179.1 C180.1 C181.1 C182.2 C183.2 C184.1 C185.2 C189.2 C190.2 C193.2 C194.2 C195.2 C196.2 C197.2 C202.2 J1.2 J1.10 J2.10 J17.5(GND) L14.1 R6.2 R8.1 R13.1 R18.2 R20.2 R23.2 R27.2 R32.1 R40.1 R45.2 R58.2 R92.1 R213.2 R293.1 U1.B2(GND) U1.B15(GND) U1.C5(GND) U1.C12(GND) U1.D5(GND) U1.D7(GND) U1.D10(GND) U1.E2(CLK0,_DIFFCLK_0P) U1.E4(GND) U1.E5(GNDA3) U1.E12(GNDA2) U1.E13(GND) U1.F1(GND) U1.F2(GND) U1.F6(GND) U1.F10(GND) U1.G4(GND) U1.G5(GND) U1.G11(GND) U1.G13(GND) U1.H7(GND) U1.H8(GND) U1.H9(GND) U1.H10(GND) U1.H15(GND) U1.H16(GND) U1.J7(GND) U1.J8(GND) U1.J9(GND) U1.J10(GND) U1.J11(GND) U1.K4(GND) U1.K6(GND) U1.K8(GND) U1.K12(GND) U1.K13(GND) U1.L9(GND) U1.L10(GND) U1.L11(GND) U1.M1(CLK3,_DIFFCLK_1N) U1.M2(CLK2,_DIFFCLK_1P) U1.M4(GND) U1.M5(GNDA1) U1.M12(GNDA4) U1.M13(GND) U1.N7(GND) U1.N10(GND) U1.P5(GND) U1.P12(GND) U1.R2(GND) U1.R8(CLK15,_DIFFCLK_6P) U1.R9(CLK13,_DIFFCLK_7P) U1.R15(GND) U1.T9(CLK12,_DIFFCLK_7N) U2.10(GND) U3.A1(GND_) U3.A13(GND_) U3.B8(GND_) U3.C3(GND_) U3.D5(GND_) U3.E11(GND_) U3.E13(IO_6_E13/CLK3N/DIFFIO_RX_R16N) U3.F3(GND_) U3.F9(IO_6_F9/DPCLK3/DIFFIO_RX_R26P) U3.F10(IO_6_F10/DPCLK2/DIFFIO_RX_R26N) U3.F13(IO_6_F13/CLK3P/DIFFIO_RX_R16P) U3.G7(GND_) U3.G9(IO_6_G9/CLK2P/DIFFIO_RX_R14P) U3.G10(IO_6_G10/CLK2N/DIFFIO_RX_R14N) U3.H4(IO_2_H4/CLK1P/DIFFIO_RX_L20P) U3.H6(IO_2_H6/CLK0P/DIFFIO_RX_L18P) U3.H12(GND_) U3.J4(GND_) U3.L9(GND_) U3.M6(GND_) U3.N1(GND_) U3.N2(IO_2_N2/DPCLK0/DIFFIO_RX_L22N) U3.N3(IO_2_N3/DPCLK1/DIFFIO_RX_L22P) U3.N13(GND_) U4.1(GND) U5.3(GND) U6.6(AGND0) U6.10(AGND1) U6.12(GND0) U6.14(RESERVED) U6.26(GND1) U6.28(GND2) U6.41(GND3) U6.53(GND4) U6.56(GND5) U6.57(EXPOSED_PAD) U13.B3(VSS2) U13.C1(VSSQ1) U13.E5(VSSQ2) Y1.2 Y1.4 ; also on sheet 11 12 13 14 15 16 17
GND_EARTH_USB: C202.1 J17.6(SHELL1) J17.7(SHELL2) J17.8(SHELL3) J17.9(SHELL4) R293.2
VCC_1.2V: L15.1 R63.2 R66.2 ; also on sheet 17
VCC_1.2V_PG: U3.H10(IO_5_H10/DIFFIO_RX_R8N) ; also on sheet 17
VCC_1.8V: C40.1 C41.2 C42.2 C43.2 C183.1 C184.2 C185.1 R236.1 R245.2 R261.2 R262.2 U13.B4(VCC) U13.D1(VCCQ1) U13.E4(VCCQ2) ; also on sheet 17
VCC_2.5V: C182.1 C189.1 R64.2 R68.2 U3.F11(VCCIO6_) U3.G11(VCCIO6_) ; also on sheet 17
VCC_3.3V: C1.1 C2.2 C6.2 C7.2 C8.2 C9.2 C10.2 C11.2 C12.2 C13.2 C16.2 C18.2 C146.1 C151.1 C153.2 C155.2 C157.2 C190.1 J1.4 J2.4 L2.1 L3.1 R9.1 R11.2 R29.2 R30.2 R33.1 R38.1 R39.1 R41.1 R42.1 R43.1 R46.1 R47.1 R50.2 R51.2 R52.2 R53.2 R54.2 R55.1 R56.1 R59.2 R60.1 R61.1 R77.2 R79.2 R214.1 R215.1 U2.2(VCC) U3.C6(VCCIO8_) U3.C7(VCCIO8_) U3.C8(VCCIO8_) U3.F7(VCC_ONE_) U3.G3(VCCIO1B_) U3.G6(VCC_ONE_) U3.G8(VCC_ONE_) U3.H7(VCC_ONE_) U3.H11(VCCIO5_) U3.J3(VCCIO2_) U3.J11(VCCIO5_) U3.K3(VCCIO2_) U3.L6(VCCIO3_) U3.L7(VCCIO3_) U3.L8(VCCIO3_) U4.4(VCC) U6.3(AVCC0) U6.7(AVCC1) U6.11(VCC0) U6.17(VCC1) U6.27(VCC2) U6.32(VCC3) U6.43(VCC4) U6.55(VCC5) ; also on sheet 11 12 13 14 15 17
VCC_3.3V_PG: U3.H13(IO_5_H13/DIFFIO_RX_R9N) ; also on sheet 17
VCCA_ISENSE: C22.2 R72.2 R85.2 U8.5(VOUT)
VCCINT_ISENSE: C20.2 R71.2 R86.2 U7.5(VOUT)
VCCIO_3.3V_ISENSE: C28.2 R81.2 R89.2 U11.5(VOUT)
24M_XTALIN: C4.1 U6.5(XTALIN) Y1.1
24M_XTALOUT: C5.1 U6.4(XTALOUT) Y1.3
A0+: C169.1 R216.2 R217.2 U32.3(VINA+)
A1+: C170.1 R218.2 R219.2 U32.5(VINB+)
A2+: C171.1 R220.2 R221.2 U33.3(VINA+)
A3+: C172.1 R222.2 R223.2 U33.5(VINB+)
A4+: C174.1 R224.2 R225.2 U34.3(VINA+)
A5+: C175.1 R226.2 R227.2 U34.5(VINB+)
A_GND: C19.1 C20.1 C22.1 C23.1 C26.1 C28.1 C29.2 C32.2 C33.2 C34.2 C35.2 C36.2 C37.2 C38.2 C39.2 C168.2 C169.2 C170.2 C171.2 C172.2 C173.2 C174.2 C175.2 C188.2 C212.2 C213.1 L14.2 R71.1 R72.1 R81.1 R216.1 R218.1 R220.1 R222.1 R224.1 R226.1 U3.E2(REFGND_) U7.4(V-) U8.4(V-) U11.4(V-) U32.4(VSS) U33.4(VSS) U34.4(VSS) ; also on sheet 12
ADC1IN1: C32.1 R84.1 U3.D1(IO_1A_D1/ADC1IN1/DIFFIO_RX_L1N)
ADC1IN2: C33.1 R85.1 U3.C2(IO_1A_C2/ADC1IN2/DIFFIO_RX_L1P)
ADC1IN3: C34.1 R86.1 U3.E3(IO_1A_E3/ADC1IN3/DIFFIO_RX_L3N)
ADC1IN4: C35.1 R87.1 U3.E4(IO_1A_E4/ADC1IN4/DIFFIO_RX_L3P)
ADC1IN5: C36.1 R88.1 U3.C1(IO_1A_C1/ADC1IN5/DIFFIO_RX_L5N)
ADC1IN6: C37.1 R89.1 U3.B1(IO_1A_B1/ADC1IN6/DIFFIO_RX_L5P)
ADC1IN7: C38.1 R90.1 U3.F1(IO_1A_F1/ADC1IN7/DIFFIO_RX_L7N)
ADC1IN8: C39.1 R91.1 U3.E1(IO_1A_E1/ADC1IN8/DIFFIO_RX_L7P)
ANAIN1: C29.1 R83.1 U3.D2(ANAIN1_)
ARDUINO_ADC_SCL: R215.2 R279.2 U1.D8(IO_B8_1) U3.L12(IO_5_L12/DIFFIO_RX_R2N)
ARDUINO_ADC_SDA: R214.2 R278.2 U1.C8(IO_B8_0) U3.K11(IO_5_K11/DIFFIO_RX_R2P)
ARDUINO_AMP0: R88.2 U32.1(VOUTA) U32.2(VINA-)
ARDUINO_AMP1: R83.2 U32.6(VINB-) U32.7(VOUTB)
ARDUINO_AMP2: R84.2 U33.1(VOUTA) U33.2(VINA-)
ARDUINO_AMP3: R91.2 U33.6(VINB-) U33.7(VOUTB)
ARDUINO_AMP4: R90.2 U34.1(VOUTA) U34.2(VINA-)
ARDUINO_AMP5: R87.2 U34.6(VINB-) U34.7(VOUTB)
ARDUINO_ANA0: R217.1 ; also on sheet 12
ARDUINO_ANA1: R219.1 ; also on sheet 12
ARDUINO_ANA2: R221.1 ; also on sheet 12
ARDUINO_ANA3: R223.1 ; also on sheet 12
ARDUINO_ANA4: R225.1 ; also on sheet 12
ARDUINO_ANA5: R227.1 ; also on sheet 12
ARDUINO_IO0: U1.B1(IO_B1_0) ; also on sheet 12
ARDUINO_IO1: U1.C2(IO,_DIFFIO_L3P) ; also on sheet 12
ARDUINO_IO2: U1.F3(IO,_VREFB1N0) ; also on sheet 12
ARDUINO_IO3: U1.D1(IO,_DIFFIO_L4N) ; also on sheet 12
ARDUINO_IO4: U1.G2(IO,_DIFFIO_L6P) ; also on sheet 12
ARDUINO_IO5: U1.G1(IO,_DIFFIO_L6N) ; also on sheet 12
ARDUINO_IO6: U1.J2(IO,_DIFFIO_L7P) ; also on sheet 12
ARDUINO_IO7: U1.J1(IO,_DIFFIO_L7N) ; also on sheet 12
ARDUINO_IO8: U1.K2(IO,_DIFFIO_L10P) ; also on sheet 12
ARDUINO_IO9: U1.K5(IO,_RUP1) ; also on sheet 12
ARDUINO_IO10: U1.L4(IO,_RDN1) ; also on sheet 12
ARDUINO_IO11: U1.K1(IO,_DIFFIO_L10N) ; also on sheet 12
ARDUINO_IO12: U1.L2(IO,_DIFFIO_L11P) ; also on sheet 12
ARDUINO_IO13: U1.L1(IO,_DIFFIO_L11N) ; also on sheet 12
ARDUINO_RSTn: R288.2 U1.L3(IO,_VREFB2N0) ; also on sheet 12
ARDUINO_SCL: R277.2 U1.N1(IO,_DIFFIO_L13N) ; also on sheet 12
ARDUINO_SDA: R276.2 U1.N2(IO,_DIFFIO_L13P) ; also on sheet 12
C10_AS_ASDO: U1.C1(IO,_DIFFIO_L3N,_DATA1,_ASDO) U2.15(DATA0)
C10_AS_CSn: U1.D2(IO,_DIFFIO_L4P,_FLASH_NCE,_NCSO) U2.7(nCS)
C10_AS_DATA0: R10.1 U1.H2(IO,_DATA0)
C10_AS_DCLK: U1.H1(DCLK) U2.16(DCLK)
C10_CLK50M: U1.E1(CLK1,_DIFFCLK_0N) ; also on sheet 15
C10_CLK_ADJ: U1.E16(CLK5,_DIFFCLK_2N) ; also on sheet 15
C10_CONF_DONE: R16.2 U1.H14(CONF_DONE) U3.L2(IO_2)
C10_CRC_ERROR: R246.2 U1.G15(IO,_DIFFIO_R5P,_CRC_ERROR) U3.M1(IO_2_M1/DIFFIO_RX_L21N)
C10_DEV_OE: R207.2 U1.J16(IO,_DIFFIO_R9N,_DEV_OE)
C10_INIT_DONE: R21.2 U1.G16(IO,_DIFFIO_R5N,_INIT_DONE) U3.K2(IO_2_K2/DIFFIO_RX_L28P)
C10_JTAG_TCK: R6.1 U1.H3(TCK) U3.E10(IO_6_E10/DIFFIO_RX_R31P)
C10_JTAG_TDI: R4.2 U1.H4(TDI) U3.A12(IO_6_A12/DIFFIO_RX_R30N)
C10_JTAG_TDO: U1.J4(TDO) U3.D12(IO_6_D12/DIFFIO_RX_R33P)
C10_JTAG_TMS: R7.2 U1.J5(TMS) U3.D9(IO_6_D9/DIFFIO_RX_R31N)
C10_M10_IO0: U1.E8(IO,_DIFFIO_T10N,_DATA2) U3.K8(IO_3_K8/DIFFIO_TX_RX_B14P)
C10_M10_IO1: U1.E7(IO,_DATA5) U3.J8(IO_3_J8/DIFFIO_TX_RX_B14N)
C10_M10_IO2: U1.F8(IO,_DIFFIO_T10P,_DATA3) U3.L10(IO_3_L10/DIFFIO_TX_RX_B16P)
C10_M10_IO3: U1.C3(IO,_PLL3_CLKOUTN) U3.L5(IO_3_L5/DIFFIO_TX_RX_B1N)
C10_MSEL0: R22.1 R23.1 U1.H13(MSEL0)
C10_MSEL1: R19.1 R20.1 U1.H12(MSEL1)
C10_MSEL2: R17.1 R18.1 U1.G12(MSEL2)
C10_NCE: R8.2 U1.J3(NCE)
C10_NCONFIG: R2.2 U1.H5(NCONFIG) ; also on sheet 14
C10_NSTATUS: R1.2 U1.F4(NSTATUS) U3.M2(IO_2_M2/DIFFIO_RX_L21P)
C10_RESETn: R136.2 U1.J15(IO,_DIFFIO_R9P,_DEV_CLRN) ; also on sheet 14
C10_RG_TXCLK: R305.2 U1.D3(IO,_PLL3_CLKOUTP)
C10_RG_TXCTL: R301.2 U1.D6(IO_B8_2)
C10_RG_TXD0: R306.2 U1.E6(IO,_DATA6)
C10_RG_TXD1: R303.2 U1.A3(IO,_DIFFIO_T2P)
C10_RG_TXD2: R304.2 U1.B3(IO_B8_3)
C10_RG_TXD3: R302.2 U1.A2(IO,_DIFFIO_T2N)
C10_USB_CLK: R248.2 U1.B9(CLK9,_DIFFCLK_5P)
C10_VCCA: L17.1 R64.1 R67.2
C10_VCCA_FLT: C117.2 L17.2 R4.1 R7.1 R17.2 R19.2 R22.2 U1.F5(VCCA3) U1.F12(VCCA2) U1.L5(VCCA1) U1.L12(VCCA4)
C10_VCCD_PLL: C115.1 R237.2 TP26.1(TP) U1.D4(VCCD_PLL3) U1.D13(VCCD_PLL2) U1.N4(VCCD_PLL1) U1.N13(VCCD_PLL4)
C10_VCCINT: C124.1 C129.1 C130.1 C134.1 C136.1 C138.2 C139.2 C141.1 C142.1 C143.2 C193.1 C194.1 R63.1 R65.2 U1.F7(VCCINT) U1.F11(VCCINT) U1.G6(VCCINT) U1.G7(VCCINT) U1.G8(VCCINT) U1.G9(VCCINT) U1.G10(VCCINT) U1.H6(VCCINT) U1.H11(VCCINT) U1.J6(VCCINT) U1.J12(VCCINT) U1.K7(VCCINT) U1.K9(VCCINT) U1.K10(VCCINT) U1.K11(VCCINT) U1.L6(VCCINT) U1.M9(VCCINT) U1.M11(VCCINT)
C10_VCCIO_1.8V: C122.2 C197.1 R12.1 R236.2 TP25.1(TP) U1.P10(VCCIO4) U1.P13(VCCIO4) U1.T16(VCCIO4)
C10_VCCIO_3.3V: C120.2 C195.1 C196.1 R1.1 R2.1 R16.1 R21.1 R77.1 R78.2 R136.1 R207.1 R246.1 R276.1 R277.1 R278.1 R279.1 R288.1 U1.A1(VCCIO8) U1.A16(VCCIO7) U1.C4(VCCIO8) U1.C7(VCCIO8) U1.C10(VCCIO7) U1.C13(VCCIO7) U1.E3(VCCIO1) U1.E14(VCCIO6) U1.G3(VCCIO1) U1.G14(VCCIO6) U1.K3(VCCIO2) U1.K14(VCCIO5) U1.M3(VCCIO2) U1.M14(VCCIO5) U1.P4(VCCIO3) U1.P7(VCCIO3) U1.T1(VCCIO3)
ENET_CLK_125M: U1.T8(CLK14,_DIFFCLK_6N) ; also on sheet 15
ENET_INT: U1.B5(IO,_DIFFIO_T5P) ; also on sheet 11
ENET_MDC: U1.B4(IO,_DIFFIO_T3P) ; also on sheet 11
ENET_MDIO: U1.A4(IO,_DIFFIO_T3N) ; also on sheet 11
ENET_RG_RXCLK: U1.B8(CLK11,_DIFFCLK_4P) ; also on sheet 11
ENET_RG_RXCTL: U1.A5(IO,_DIFFIO_T5N,_DATA7) ; also on sheet 11
ENET_RG_RXD0: U1.A7(IO,_DIFFIO_T9N) ; also on sheet 11
ENET_RG_RXD1: U1.B7(IO,_DIFFIO_T9P,_DATA4) ; also on sheet 11
ENET_RG_RXD2: U1.A6(IO,_DIFFIO_T7N) ; also on sheet 11
ENET_RG_RXD3: U1.B6(IO,_DIFFIO_T7P) ; also on sheet 11
ENET_RG_TXCLK: R305.1 ; also on sheet 11
ENET_RG_TXCTL: R301.1 ; also on sheet 11
ENET_RG_TXD0: R306.1 ; also on sheet 11
ENET_RG_TXD1: R303.1 ; also on sheet 11
ENET_RG_TXD2: R304.1 ; also on sheet 11
ENET_RG_TXD3: R302.1 ; also on sheet 11
ENET_RSTn: U1.C6(IO,_VREFB8N0) ; also on sheet 11
EXT_JTAG_TCK: J2.1 R57.2 R58.1 U3.J12(IO_5_J12/DIFFIO_RX_R7N)
EXT_JTAG_TDI: J2.9 R61.2 U3.J9(IO_5_J9/DIFFIO_RX_R8P)
EXT_JTAG_TDO: J2.3 U3.K12(IO_5_K12/DIFFIO_RX_R7P)
EXT_JTAG_TMS: J2.5 R60.2 U3.L13(IO_5)
EXT_VREF: C212.1 C213.2 R228.1 U3.D3(ADC_VREF_) ; also on sheet 12
EXT_VREF_AR: R228.2 ; also on sheet 12
FX2_D_N: J17.2(D-) U5.2(D-) U6.9(DMINUS)
FX2_D_P: J17.3(D+) U5.1(D+) U6.8(DPLUS)
FX2_FLAGA: U3.M9(IO_3_M9/DIFFIO_RX_B8P) U6.29(CTL0)
FX2_FLAGB: U3.N8(IO_3_N8/DIFFIO_RX_B6P) U6.30(CTL1)
FX2_FLAGC: U3.M8(IO_3_M8/DIFFIO_RX_B8N) U6.31(CTL2)
FX2_PA0: U3.N7(IO_3_N7/DIFFIO_RX_B6N) U6.33(PA0)
FX2_PA1: U3.M7(IO_3_M7/DIFFIO_TX_RX_B5P) U6.34(PA1)
FX2_PA2: U3.N6(IO_3_N6/DIFFIO_TX_RX_B5N) U6.35(PA2)
FX2_PA3: U3.N5(IO_3_N5/DIFFIO_RX_B4P) U6.36(PA3)
FX2_PA4: U3.M5(IO_3_M5/DIFFIO_RX_B2P) U6.37(PA4)
FX2_PA5: U3.N4(IO_3_N4/DIFFIO_RX_B4N) U6.38(PA5)
FX2_PA6: U3.M4(IO_3_M4/DIFFIO_RX_B2N) U6.39(PA6)
FX2_PA7: U3.M3(IO_2_M3/PLL_L_CLKOUTN/DIFFIO_RX_L27N) U6.40(PA7)
FX2_PB0: U3.M13(IO_3_M13/DIFFIO_TX_RX_B10N) U6.18(PB0)
FX2_PB1: U3.M12(IO_3_M12/DIFFIO_TX_RX_B10P) U6.19(PB1)
FX2_PB2: U3.N12(IO_3) U6.20(PB2)
FX2_PB3: U3.M11(IO_3_M11/DIFFIO_TX_RX_B12N) U6.21(PB3)
FX2_PB4: U3.L11(IO_3_L11/DIFFIO_TX_RX_B12P) U6.22(PB4)
FX2_PB5: U3.N10(IO_3_N10/DIFFIO_RX_B11N) U6.23(PB5)
FX2_PB6: U3.M10(IO_3_M10/DIFFIO_TX_RX_B16N) U6.24(PB6)
FX2_PB7: U3.N9(IO_3_N9/DIFFIO_RX_B11P) U6.25(PB7)
FX2_PD0: R35.1 U6.45(PD0)
FX2_PD1: R34.1 U6.46(PD1)
FX2_PD2: R36.1 U6.47(PD2)
FX2_PD3: R37.1 U6.48(PD3)
FX2_PD4: U3.J7(IO_3_J7/DIFFIO_TX_RX_B9N) U6.49(PD4)
FX2_PD5: U3.K7(IO_3_K7/DIFFIO_TX_RX_B9P) U6.50(PD5)
FX2_PD6: U3.J5(IO_3_J5/DIFFIO_TX_RX_B3P) U6.51(PD6)
FX2_PD7: U3.L4(IO_3_L4/DIFFIO_TX_RX_B1P) U6.52(PD7)
FX2_RESETn: R27.1 U3.J1(IO_2_J1/DIFFIO_RX_L19N) U4.2(~{RESET}) U6.42(~{RESET})
FX2_SCL: R29.1 U3.J6(IO_3_J6/DIFFIO_TX_RX_B7N) U6.15(SCL)
FX2_SDA: R26.2 R30.1 U6.16(SDA)
FX2_SLRDn: U3.K5(IO_3_K5/DIFFIO_TX_RX_B3N) U6.1(RDY0)
FX2_SLWRn: U3.L3(IO_2_L3/PLL_L_CLKOUTP/DIFFIO_RX_L27P) U6.2(RDY1)
FX2_WAKEUP: C14.2 R31.2 R32.2 U6.44(WAKEUP)
GPIO0: U1.L13(IO_B5_0) ; also on sheet 13
GPIO1: U1.L16(IO,_DIFFIO_R11N) ; also on sheet 13
GPIO2: U1.L15(IO,_DIFFIO_R11P) ; also on sheet 13
GPIO3: U1.K16(IO,_DIFFIO_R10N) ; also on sheet 13
GPIO4: U1.P16(IO,_DIFFIO_R15N) ; also on sheet 13
GPIO5: U1.R16(IO,_DIFFIO_R15P) ; also on sheet 13
GPIO6: U1.N16(IO,_DIFFIO_R13N) ; also on sheet 13
GPIO7: U1.N15(IO,_DIFFIO_R13P) ; also on sheet 13
GPIO8: U1.N14(IO,_RUP3) ; also on sheet 13
GPIO9: U1.P15(IO,_RDN3) ; also on sheet 13
GPIO10: U1.N8(IO_B3_6) ; also on sheet 13
GPIO11: U1.P8(IO_B3_7) ; also on sheet 13
GPIO12: U1.M8(IO_B3_5) ; also on sheet 13
GPIO13: U1.L8(IO_B3_4) ; also on sheet 13
GPIO14: U1.R7(IO,_DIFFIO_B8P) ; also on sheet 13
GPIO15: U1.T7(IO,_DIFFIO_B8N) ; also on sheet 13
GPIO16: U1.L7(IO_B3_3) ; also on sheet 13
GPIO17: U1.M7(IO_B3_2) ; also on sheet 13
GPIO18: U1.R6(IO,_DIFFIO_B7P) ; also on sheet 13
GPIO19: U1.T6(IO,_DIFFIO_B7N) ; also on sheet 13
GPIO20: U1.T2(IO_B3_0) ; also on sheet 13
GPIO21: U1.M6(IO_B3_1) ; also on sheet 13
GPIO22: U1.R5(IO,_DIFFIO_B6P) ; also on sheet 13
GPIO23: U1.T5(IO,_DIFFIO_B6N) ; also on sheet 13
GPIO24: U1.N5(IO,_DIFFIO_B4P) ; also on sheet 13
GPIO25: U1.N6(IO,_DIFFIO_B4N) ; also on sheet 13
GPIO26: U1.R4(IO,_PLL1_CLKOUTP) ; also on sheet 13
GPIO27: U1.T4(IO,_PLL1_CLKOUTN) ; also on sheet 13
GPIO28: U1.N3(IO,_DIFFIO_B1P) ; also on sheet 13
GPIO29: U1.P3(IO,_DIFFIO_B1N) ; also on sheet 13
GPIO30: U1.R3(IO,_DIFFIO_B2P) ; also on sheet 13
GPIO31: U1.T3(IO,_DIFFIO_B2N) ; also on sheet 13
GPIO32: U1.P6(IO,_VREFB3N0) ; also on sheet 13
GPIO33: U1.P2(IO,_DIFFIO_L15P) ; also on sheet 13
GPIO34: U1.P1(IO,_DIFFIO_L15N) ; also on sheet 13
GPIO35: U1.R1(IO_B2_0) ; also on sheet 13
HBUS_CKn: R243.1 U1.R14(IO,_PLL4_CLKOUTN) U13.B1(CK#)
HBUS_CKp: R243.2 U1.P14(IO,_PLL4_CLKOUTP) U13.B2(CK)
HBUS_CLK_50M: U1.M15(CLK6,_DIFFCLK_3P) ; also on sheet 15
HBUS_CS1n: R258.2 U1.N12(IO_B4_2)
HBUS_CS2n: U1.P9(IO_B4_1) U13.A3(CS#)
HBUS_DQ0: R249.1 U1.T12(IO,_DIFFIO_B18N)
HBUS_DQ1: R250.1 U1.T13(IO,_DIFFIO_B20N)
HBUS_DQ2: R251.1 U1.T11(IO,_DIFFIO_B17N)
HBUS_DQ3: R252.1 U1.R10(IO,_DIFFIO_B16P)
HBUS_DQ4: R253.1 U1.T10(IO,_DIFFIO_B16N)
HBUS_DQ5: R254.1 U1.R11(IO,_DIFFIO_B17P)
HBUS_DQ6: R255.1 U1.R12(IO,_DIFFIO_B18P)
HBUS_DQ7: R256.1 U1.R13(IO,_DIFFIO_B20P)
HBUS_INTn: R260.2 R262.1 U1.P11(IO,_VREFB4N0)
HBUS_RSTn: R245.1 U1.N9(IO_B4_0) U13.A4(RESET#)
HBUS_RSTOn: R259.2 R261.1 U1.T15(IO,_DIFFIO_B23N)
HBUS_RWDS: R257.1 U1.T14(IO,_DIFFIO_B23P)
M10_CLK50M: U3.H5(IO_2_H5/CLK1N/DIFFIO_RX_L20N) ; also on sheet 15
M10_CONF_DONE: R43.2 U3.C5(IO_8_C5/CONF_DONE/DIFFIO_RX_T24N)
M10_CONFIG_SEL: R40.2 R50.1 U3.D7(IO_8_D7/CONFIG_SEL)
M10_DEV_CLRn: R38.2 U3.B9(IO_8_B9/DEV_CLRN/DIFFIO_RX_T16N)
M10_DEV_OE: R39.2 U3.D8(IO_8_D8/DEV_OE/DIFFIO_RX_T18P)
M10_JTAGEN: R33.2 U3.E5(IO_1B_E5/JTAGEN)
M10_NCONFIG: R41.2 U3.E7(INPUT_ONLY_8_E7/NCONFIG)
M10_NSTATUS: R42.2 U3.C4(IO_8_C4/NSTATUS/DIFFIO_RX_T24P)
M10_TCK: J1.1 R35.2 R44.2 R45.1 U3.G2(IO_1B_G2/TCK/DIFFIO_RX_L11P)
M10_TDI: J1.9 R36.2 R47.2 U3.F5(IO_1B_F5/TDI/DIFFIO_RX_L12N)
M10_TDO: J1.3 R37.2 U3.F6(IO_1B_F6/TDO/DIFFIO_RX_L12P)
M10_TMS: J1.5 R34.2 R46.2 U3.G1(IO_1B_G1/TMS/DIFFIO_RX_L11N)
M10_USB_CLK: R247.1 U3.G5(IO_2_G5/CLK0N/DIFFIO_RX_L18N)
M10_VCCA_3.3V: C19.2 C23.2 C26.2 C168.1 C173.1 C177.1 C178.2 C179.2 C180.2 C181.2 C188.1 L3.2 U3.D4(VCCA3_) U3.D10(VCCA2_) U3.K4(VCCA1_) U3.K9(VCCA4_) U7.2(V+) U8.2(V+) U11.2(V+) U32.8(VDD) U33.8(VDD) U34.8(VDD)
M10_VCCIO1A: C156.1 C176.1 L2.2 U3.F2(VCCIO1A_)
MAX_SDA: R26.1 U3.K6(IO_3_K6/DIFFIO_TX_RX_B7P)
PMOD_D0: U1.D16(IO_B6_2) ; also on sheet 13
PMOD_D1: U1.F13(IO_B6_0) ; also on sheet 13
PMOD_D2: U1.D15(IO_B6_3) ; also on sheet 13
PMOD_D3: U1.F16(IO,_DIFFIO_R4N,_NCEO) ; also on sheet 13
PMOD_D4: U1.C16(IO,_DIFFIO_R1N) ; also on sheet 13
PMOD_D5: U1.F15(IO,_DIFFIO_R4P,_CLKUSR) ; also on sheet 13
PMOD_D6: U1.C15(IO,_DIFFIO_R1P) ; also on sheet 13
PMOD_D7: U1.B16(IO_B6_1) ; also on sheet 13
PWR_GD_LED: U3.H9(IO_5_H9/DIFFIO_RX_R10P) ; also on sheet 14
RDN2: R13.2 U1.N11(IO,_RDN2)
RUP2: R12.2 U1.M10(IO,_RUP2)
SYS_CONF_DONE: U3.K1(IO_2_K1/DIFFIO_RX_L28N) ; also on sheet 14
SYS_I2C_SCL: R55.2 U3.G13(IO_5_G13/DIFFIO_RX_R11P) ; also on sheet 15
SYS_I2C_SDA: R56.2 U3.H8(IO_5_H8/DIFFIO_RX_R10N) ; also on sheet 15
USB_5V: J17.1(VBUS) R31.1 ; also on sheet 16
USB_ADDR0: U1.A10(IO,_DIFFIO_T16N) U3.A7(IO_8_A7/DIFFIO_RX_T19P)
USB_ADDR1: U1.A11(IO,_DIFFIO_T20N) U3.A10(IO_8_A10/DIFFIO_RX_T17P)
USB_CLK: R247.2 R248.1 U6.13(IFCLK)
USB_DATA0: U1.A15(IO_B7_0) U3.A3(IO_8_A3/DIFFIO_RX_T21N)
USB_DATA1: U1.B14(IO,_PLL2_CLKOUTP) U3.B3(IO_8_B3/DIFFIO_RX_T23P)
USB_DATA2: U1.A14(IO,_PLL2_CLKOUTN) U3.A4(IO_8_A4/DIFFIO_RX_T21P)
USB_DATA3: U1.B13(IO,_DIFFIO_T22P) U3.B4(IO_8_B4/DIFFIO_RX_T23N)
USB_DATA4: U1.A13(IO,_DIFFIO_T22N) U3.A5(IO_8)
USB_DATA5: U1.B12(IO,_DIFFIO_T21P) U3.B5(IO_8_B5/DIFFIO_RX_T20N)
USB_DATA6: U1.A12(IO,_DIFFIO_T21N) U3.A6(IO_8_A6/DIFFIO_RX_T19N)
USB_DATA7: U1.B10(IO,_DIFFIO_T16P) U3.B6(IO_8_B6/DIFFIO_RX_T20P)
USB_DISABLEn: J2.2 R59.1 U3.J13(IO_5_J13/DIFFIO_RX_R9P)
USB_EMPTY: R52.1 U1.D14(IO,_DIFFIO_T24P) U3.E6(IO_8_E6/DIFFIO_RX_T22P)
USB_FULL: R51.1 U1.D12(IO,_DIFFIO_T23P) U3.C9(IO_8_C9/DIFFIO_RX_T14N)
USB_OEn: U1.F9(IO_B7_1) U3.A9(IO_8_A9/DIFFIO_RX_T15N)
USB_RDn: U1.D11(IO,_DIFFIO_T23N) U3.B10(IO_8_B10/DIFFIO_RX_T16P)
USB_RESETn: U1.C9(IO,_DIFFIO_T15N) U3.A8(IO_8_A8/DIFFIO_RX_T15P)
USB_SCL: R54.1 U1.C14(IO,_DIFFIO_T24N) U3.E8(IO_8_E8/DIFFIO_RX_T18N)
USB_SDA: R53.1 U1.E9(IO_B7_2) U3.C10(IO_8_C10/DIFFIO_RX_T14P)
USB_WRn: U1.B11(IO,_DIFFIO_T20P) U3.A11(IO_8_A11/DIFFIO_RX_T17N)
USER_DIP0: U1.M16(CLK7,_DIFFCLK_3N) ; also on sheet 14
USER_DIP1: U1.A8(CLK10,_DIFFCLK_4N) ; also on sheet 14
USER_DIP2: U1.A9(CLK8,_DIFFCLK_5N) ; also on sheet 14
USER_LED0: U1.L14(IO,_VREFB5N0) ; also on sheet 14
USER_LED1: U1.K15(IO,_DIFFIO_R10P) ; also on sheet 14
USER_LED2: U1.J14(IO_B5_1) ; also on sheet 14
USER_LED3: U1.J13(IO_B5_2) ; also on sheet 14
USER_PB0: U1.E15(CLK4,_DIFFCLK_2P) ; also on sheet 14
USER_PB1: U1.F14(IO,_VREFB6N0) ; also on sheet 14
USER_PB2: U1.C11(IO,_VREFB7N0) ; also on sheet 14
USER_PB3: U1.D9(IO,_DIFFIO_T15P) ; also on sheet 14
VTAP_BYPASSn: U3.K10(IO_5_K10/DIFFIO_RX_R1P) ; also on sheet 14
N16637352: R92.2 U13.A1(VSS1/DNP)
N16798884: C15.2 R44.1
N16863501: R65.1 U7.1(-IN)
N16863513: R66.1 U7.8(+IN)
N16863764: R67.1 U8.1(-IN)
N16863768: R68.1 U8.8(+IN)
N16887336: R11.1 U2.9(VCC/DATA2)
N16887348: R9.2 U2.1(VCC/DATA3)
N16887422: R10.2 U2.8(DATA1)
N16993975: J17.4(ID) R213.1
N17040639: R79.1 U11.8(+IN)
N17040659: R78.1 U11.1(-IN)
N17132385: R249.2 U13.D3(DQ0)
N17132392: R250.2 U13.D2(DQ1)
N17132399: R251.2 U13.C4(DQ2)
N17132406: R252.2 U13.D4(DQ3)
N17132413: R253.2 U13.D5(DQ4)
N17132420: R254.2 U13.E3(DQ5)
N17132427: R255.2 U13.E2(DQ6)
N17132434: R256.2 U13.E1(DQ7)
N17132441: R257.2 U13.C3(RWDS)
N17204392: R258.1 U13.C2(RFU4)
N17217821: R259.1 U13.A2(RFU1)
N17217865: R260.1 U13.A5(RFU2)
N17451710: C17.2 R57.1
N17533679: L15.2 R237.1 TP27.1(TP)

Not connected (* = marked no-connect by the designer): J1 6* 7* 8*; J2 6* 7* 8*; U1 E10(IO,_RDN4)* E11(IO,_RUP4)*; U2 3(NC1)* 4(NC2)* 5(NC3)* 6(NC4)* 11(NC5)* 12(NC6)* 13(NC7)* 14(NC8)*; U3 A2(IO_8_A2/DIFFIO_RX_T26P) B2(IO_8_B2/DIFFIO_RX_T26N) B7(IO_8_B7/VREFB8N0)* B11(IO_6_B11/DIFFIO_RX_R28N)* B12(IO_6_B12/DIFFIO_RX_R28P)* B13(IO_6_B13/DIFFIO_RX_R30P)* C11(IO_6_C11/DIFFIO_RX_R29N)* C12(IO_6_C12/DIFFIO_RX_R29P)* C13(IO_6)* D6(IO_8_D6/CRC_ERROR/DIFFIO_RX_T22N)* D11(IO_6_D11/DIFFIO_RX_R33N)* D13(IO_6_D13/VREFB6N0)* E9(IO_6_E9/DIFFIO_RX_R27N)* E12(IO_6_E12/DIFFIO_RX_R18N)* F4(IO_1B_F4/DIFFIO_RX_L14N) F8(IO_6_F8/DIFFIO_RX_R27P)* F12(IO_6_F12/DIFFIO_RX_R18P)* G4(IO_1B_G4/DIFFIO_RX_L14P) G12(IO_5_G12/DIFFIO_RX_R11N) H1(IO_1B_H1/VREFB1N0)* H2(IO_1B_H2/DIFFIO_RX_L16N) H3(IO_1B_H3/DIFFIO_RX_L16P) J2(IO_2_J2/DIFFIO_RX_L19P) J10(IO_5_J10/DIFFIO_RX_R1N) K13(IO_5_K13/VREFB5N0)* L1(IO_2_L1/VREFB2N0)* N11(IO_3_N11/VREFB3N0)*; U4 3(~{MR})*; U6 54(CLKOUT)*; U7 3(NC1)* 6(NC2)* 7(NC3)*; U8 3(NC1)* 6(NC2)* 7(NC3)*; U11 3(NC1)* 6(NC2)* 7(NC3)*; U13 B5(RFU3)* C5(RFU5)*

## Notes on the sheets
sheet 1
- REV
- DATE
- PAGES
- DESCRIPTION
- NOTES:
- 1.
- Project Drawing Numbers:
       Raw PCB
       Gerber Files
       PCB Design Files
       Assembly Drawing
       Fab Drawing
       Schematic Drawing
       PCB Film
       Bill of Materials
       Schematic Design Files
       Functional Specification
       PCB Layout Guidelines
       Assembly Rework
- A1
- 08/16/17
- All
- Initial Release
- 100-0321321-A1
  110-0321321-A1
  120-0321321-A1
  130-0321321-A1
  140-0321321-A1
  150-0321321-A1
  160-0321321-A1
  170-0321321-A1
  180-0321321-A1
  210-0321321-A1
  220-0321321-A1
  320-0321321-A1
- PAGE
- DESCRIPTION
- 1
- Title, Notes, Block Diagram, Rev. History
- 2
- Power Diagram
- 3
- Clock Daigram
- 4
- Cyclone 10 Bank 1~4
- 5
- Cyclone 10 Bank 5~8
- 6
- Cyclone 10 Power
- 7
- MAX10 - UBII-A
- 8
- MAX10 - UBII-B
- 9
- MAX10 - ADC
- 10
- HyperRAM
- 11
- Ethernet
- 12
- Arduino Header
- 13
- PMOD, 2x20 GPIO
- 14
- LED, PB, DIP SW
- 15
- Clock
- 16
- Power Input
- 17
- 1.2V, 1.8V, 2.5V, 3.3V
sheet 4
- EP4CE22U14I7N
- HyperRAM (HyperBUS)
- VCCIO1=3.3V
- VCCIO2=3.3V
- Reserved For MCP/Flash
- E2 is GND on CIV E U256
- C10 JTAG
- Arduino Digital IO
- VCCIO3=3.3V
- Arduino I2C
- VCCIO4=1.8V
- Clocks
- 2x20 GPIO
sheet 5
- C10 M10 Interconnetion
- 2.5V
- VCCIO5=3.3V
- C10 Misc. Signals
- VCCIO6=3.3V
- MSEL[2:0]=101: ASx1, Fast POR, 3.3V IO
- Arduino ADC I2C
- Ethernet
- VCCIO7=3.3V
- VCCIO8=3.3V
- MAX10 USB Interface
- User PBs, LEDs, SWs
- Clock
- 2x20 GPIO
- PMOD
sheet 6
- 1.2V
- 2.5V
- 1.2V
- D5, F1, F2, G5 are IO on CIV E U256
sheet 7
- USB: 90Ohm Differential Pair
- C10 M10 Interconnetion
- C10 Misc. Signals
sheet 8
- MAX10 USB Interface
- VCCIO=2.5V
- System I2C
- USB Blaster Programming Header
- C10 JTAG
- (uses JTAG mode only)
- Arduino ADC I2C
- Power Good
sheet 9
- Arduino Analog IO
sheet 10
- 1.8V I/O
- HyperRAM (HyperBUS)
- Reserved For MCP/Flash
- HBUS_CS1n: For Flash (Reserved)
  HBUS_CS2n: For RAM
- Reserved For MCP/Flash
- In customer's design, please consult with HyperRAM vendor
  to decide if need to assemble this parallel resister (R243) with
  specified HyperRAM design
